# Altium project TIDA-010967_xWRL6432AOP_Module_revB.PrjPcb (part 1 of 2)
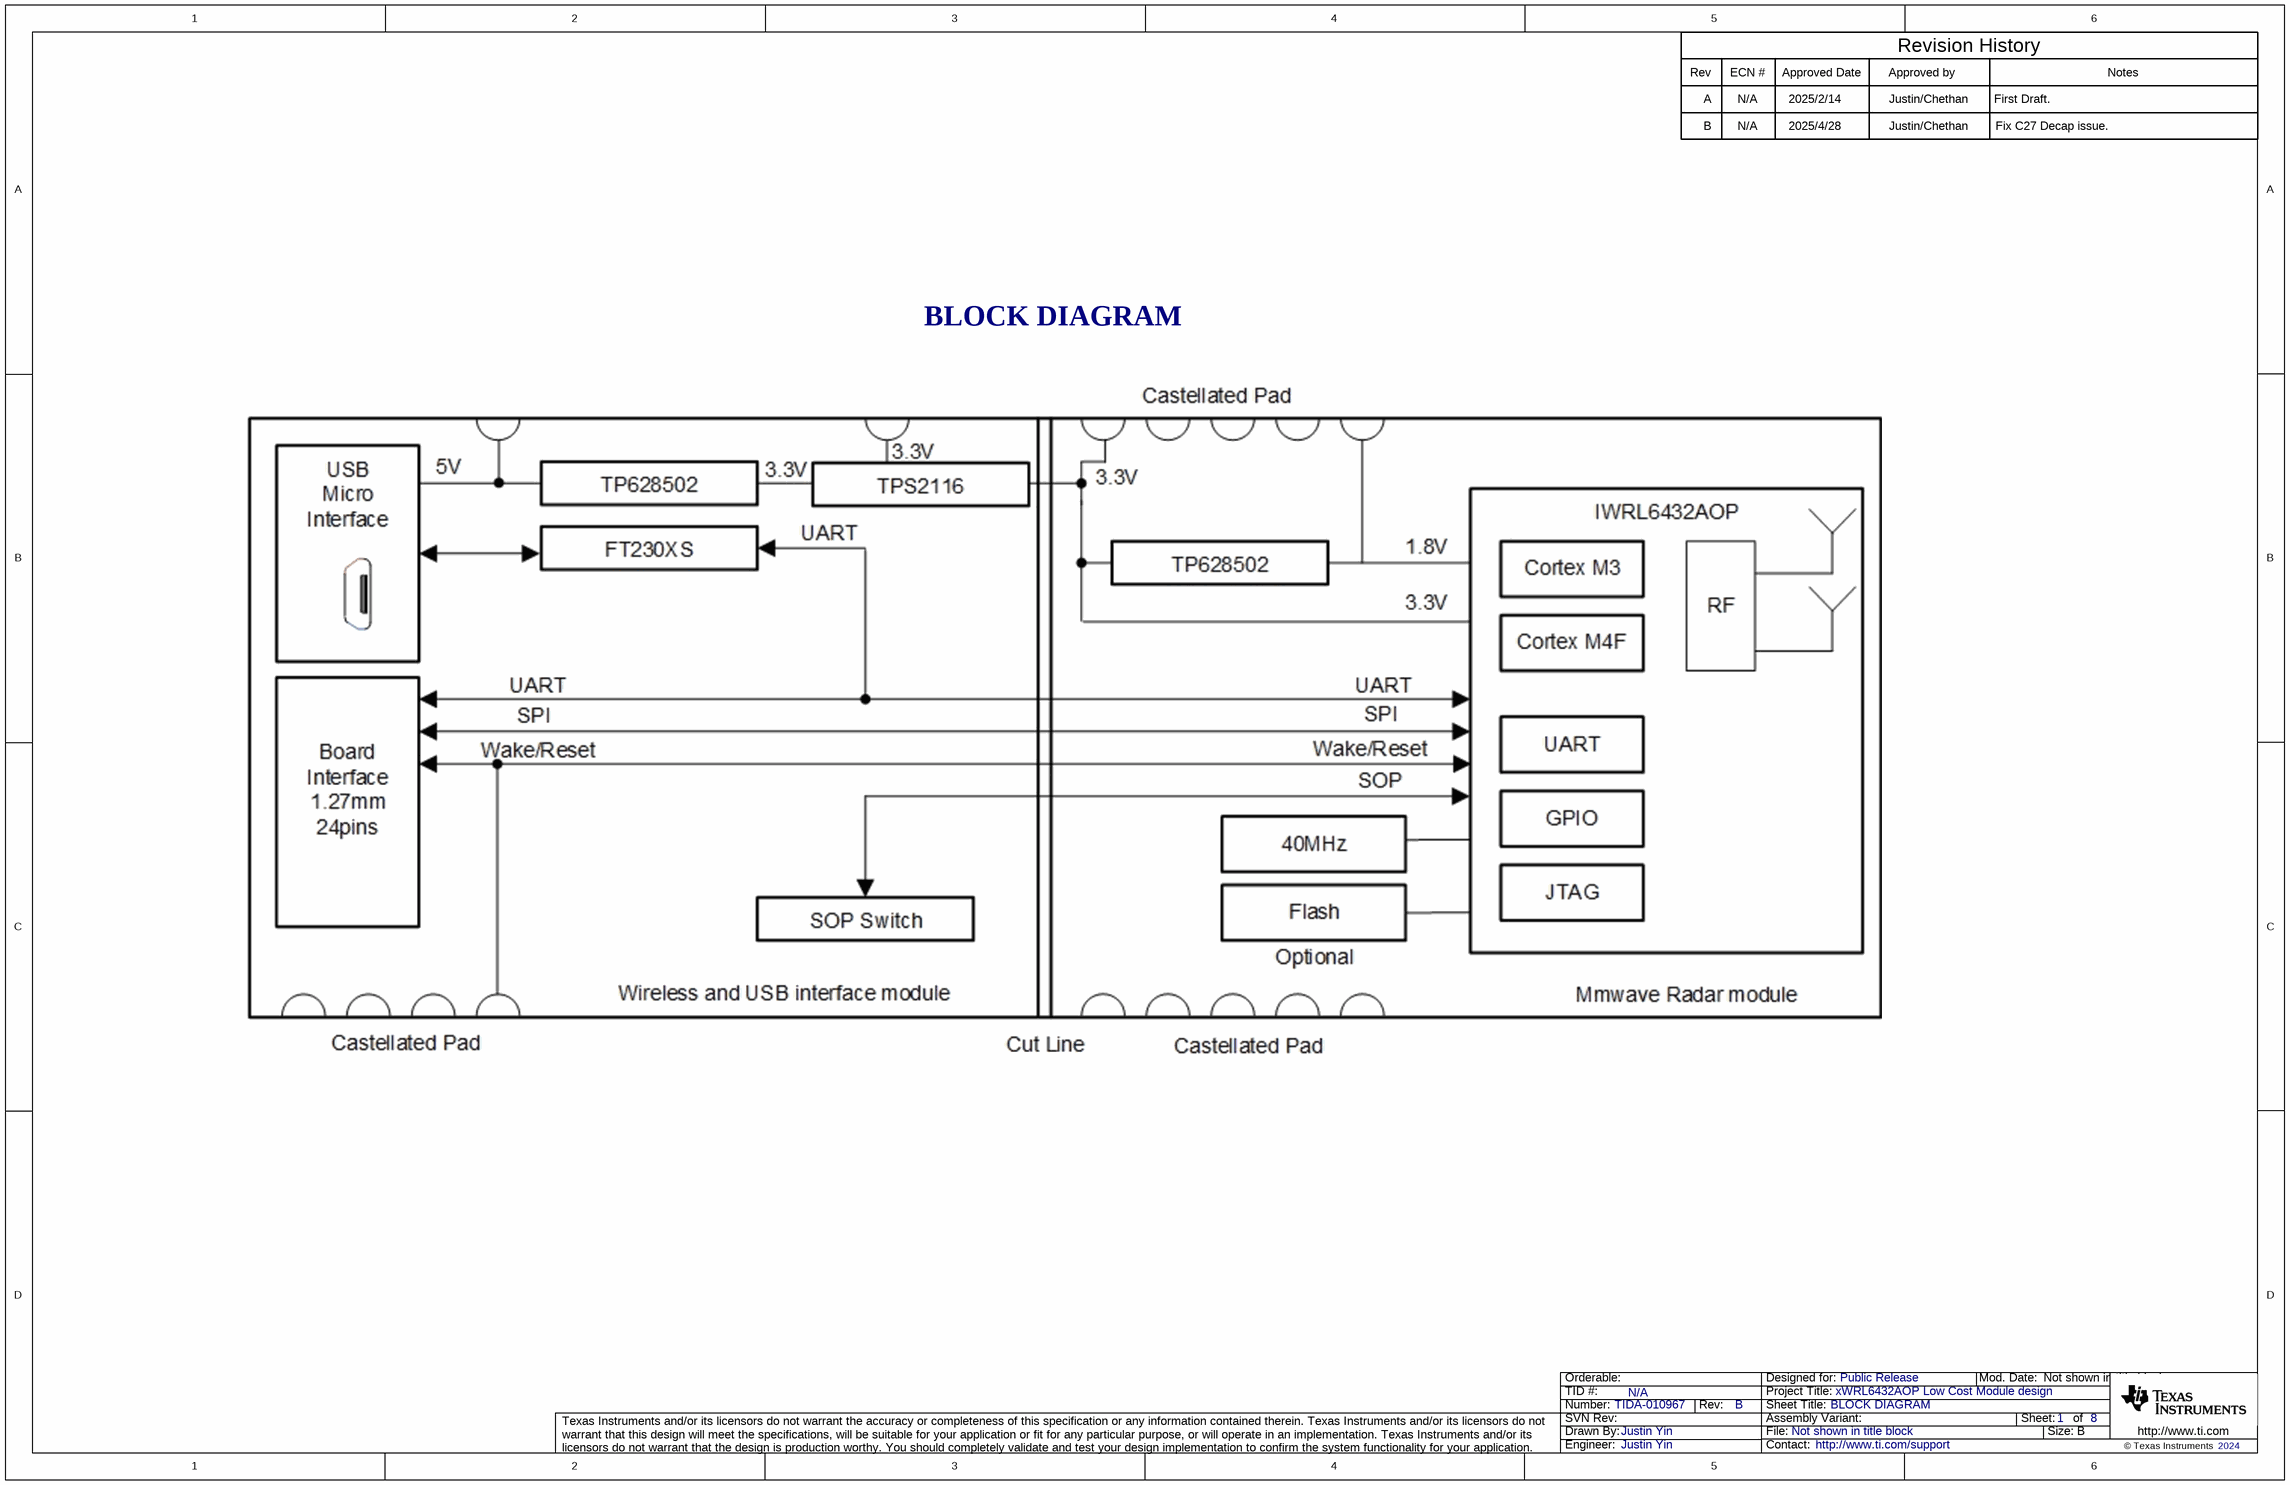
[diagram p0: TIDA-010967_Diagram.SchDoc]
CopyrightYear: 2024; PCB_Layout: Justin Yin; PCB_Rev: B; PRJ_Customer: Public Release; PRJ_Engineer: Justin Yin; PRJ_Number: TIDA-010967; PRJ_Title: xWRL6432AOP Low Cost Module design; SCH_Rev: B; TechSupport: http://www.ti.com/support; TID: N/A
8 sheets, 179 parts. Net scope: flat (ports and power ports of the same name join across sheets).
Board file: TIDA-010967_PCB.PcbDoc
Sheets:
  TIDA-010967_Diagram.SchDoc
  TIDA-010967_Table_Of_Contents.SchDoc
  TIDA-010967_USB_PWR_Connector.SchDoc
  TIDA-010967_DC_Regulators.SchDoc
  TIDA-010967_xWRL6432_Chip.SchDoc
  TIDA-010967_Decoupling_caps.SchDoc
  TIDA-010967_QSPI_Flash.SchDoc
  TIDA-010967_Hardware.SchDoc

## Sheet TIDA-010967_Diagram.SchDoc: BLOCK DIAGRAM
size 431 x 279 mm; Date: Not shown in title block; ApprovedBy: Not shown in title block; CheckedBy: Not shown in title block; Author: Not shown in title block; CompanyName: Not shown in title block; DrawnBy: Justin Yin; Organization: Not shown in title block; Address1: Not shown in title block; Address2: Not shown in title block; Address3: Not shown in title block; Address4: Not shown in title block; DocumentNumber: 1; Revision: Use project parameter SCH_Rev; SheetNumber: 1; SheetTotal: 8; PageSetup: Record=PageOptions¦CenterHorizontal=True¦CenterVertical=True¦PrintScale=1.00¦XCorrection=1.00¦YCorrection=1.00¦PrintKind=0¦BorderSize=5000000¦LeftOffset=0¦BottomOffset=0¦Orientation=2¦PaperLength=1000¦PaperWidth=1000¦Scale=100¦PaperSource=15¦PrintQuality=600¦MediaType=1¦DitherType=10¦PaperKind=Letter¦PrintScaleMode=1

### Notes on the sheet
- Rev
- A
- ECN #
- N/A
- 2025/2/14
- Approved Date
- Approved by
- Justin/Chethan
- Revision History
- First Draft.
- Notes
- B
- 2025/4/28
- Fix C27 Decap issue.
- BLOCK DIAGRAM

## Sheet TIDA-010967_Table_Of_Contents.SchDoc: TABLE OF CONTENTS
size 431 x 279 mm; Date: Not shown in title block; ApprovedBy: Not shown in title block; CheckedBy: Not shown in title block; Author: Not shown in title block; CompanyName: Not shown in title block; DrawnBy: Justin Yin; Engineer: Not shown in title block; Organization: Not shown in title block; Address1: Not shown in title block; Address2: Not shown in title block; Address3: Not shown in title block; Address4: Not shown in title block; DocumentNumber: 2; Revision: Use project parameter SCH_Rev; SheetNumber: 2; SheetTotal: 8; PageSetup: Record=PageOptions¦CenterHorizontal=True¦CenterVertical=True¦PrintScale=1.00¦XCorrection=1.00¦YCorrection=1.00¦PrintKind=0¦BorderSize=5000000¦LeftOffset=0¦BottomOffset=0¦Orientation=2¦PaperLength=1000¦PaperWidth=1000¦Scale=100¦PaperSource=15¦PrintQuality=600¦MediaType=1¦DitherType=10¦PaperKind=Letter¦PrintScaleMode=1
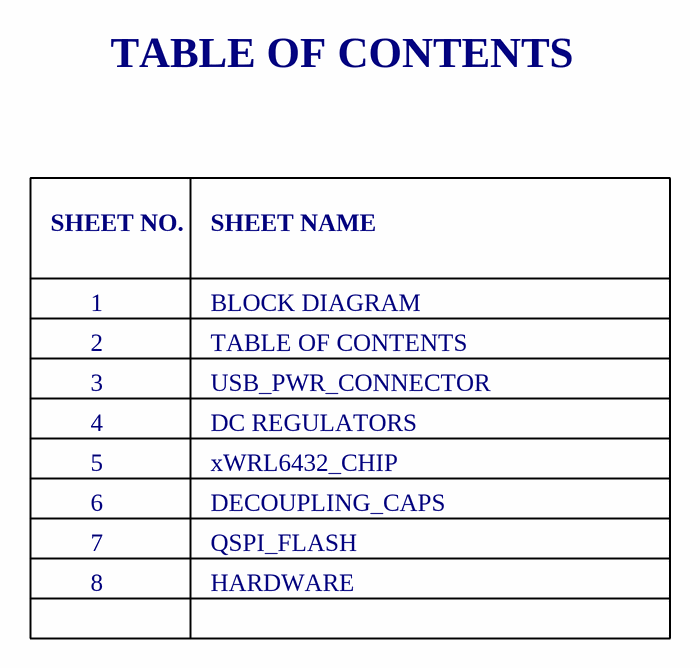
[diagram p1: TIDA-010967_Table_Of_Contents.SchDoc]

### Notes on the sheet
- TABLE OF CONTENTS
- SHEET NO.
- SHEET NAME
- 1
- 2
- 3
- BLOCK DIAGRAM
- USB_PWR_CONNECTOR
- 4
- 5
- DC REGULATORS
- xWRL6432_CHIP
- 7
- 8
- 6
- DECOUPLING_CAPS
- QSPI_FLASH
- HARDWARE

## Sheet TIDA-010967_USB_PWR_Connector.SchDoc: USB_PWR_Connector
size 431 x 279 mm; Date: Not shown in title block; ApprovedBy: Not shown in title block; CheckedBy: Not shown in title block; Author: Not shown in title block; CompanyName: Not shown in title block; DrawnBy: Justin Yin; Engineer: Not shown in title block; Organization: Not shown in title block; Address1: Not shown in title block; Address2: Not shown in title block; Address3: Not shown in title block; Address4: Not shown in title block; DocumentNumber: 3; Revision: Use project parameter SCH_Rev; SheetNumber: 3; SheetTotal: 8; PageSetup: Record=PageOptions¦CenterHorizontal=True¦CenterVertical=True¦PrintScale=1.00¦XCorrection=1.00¦YCorrection=1.00¦PrintKind=0¦BorderSize=5000000¦LeftOffset=0¦BottomOffset=0¦Orientation=2¦PaperLength=1000¦PaperWidth=1000¦Scale=100¦PaperSource=15¦PrintQuality=600¦MediaType=1¦DitherType=10¦PaperKind=Letter¦PrintScaleMode=1
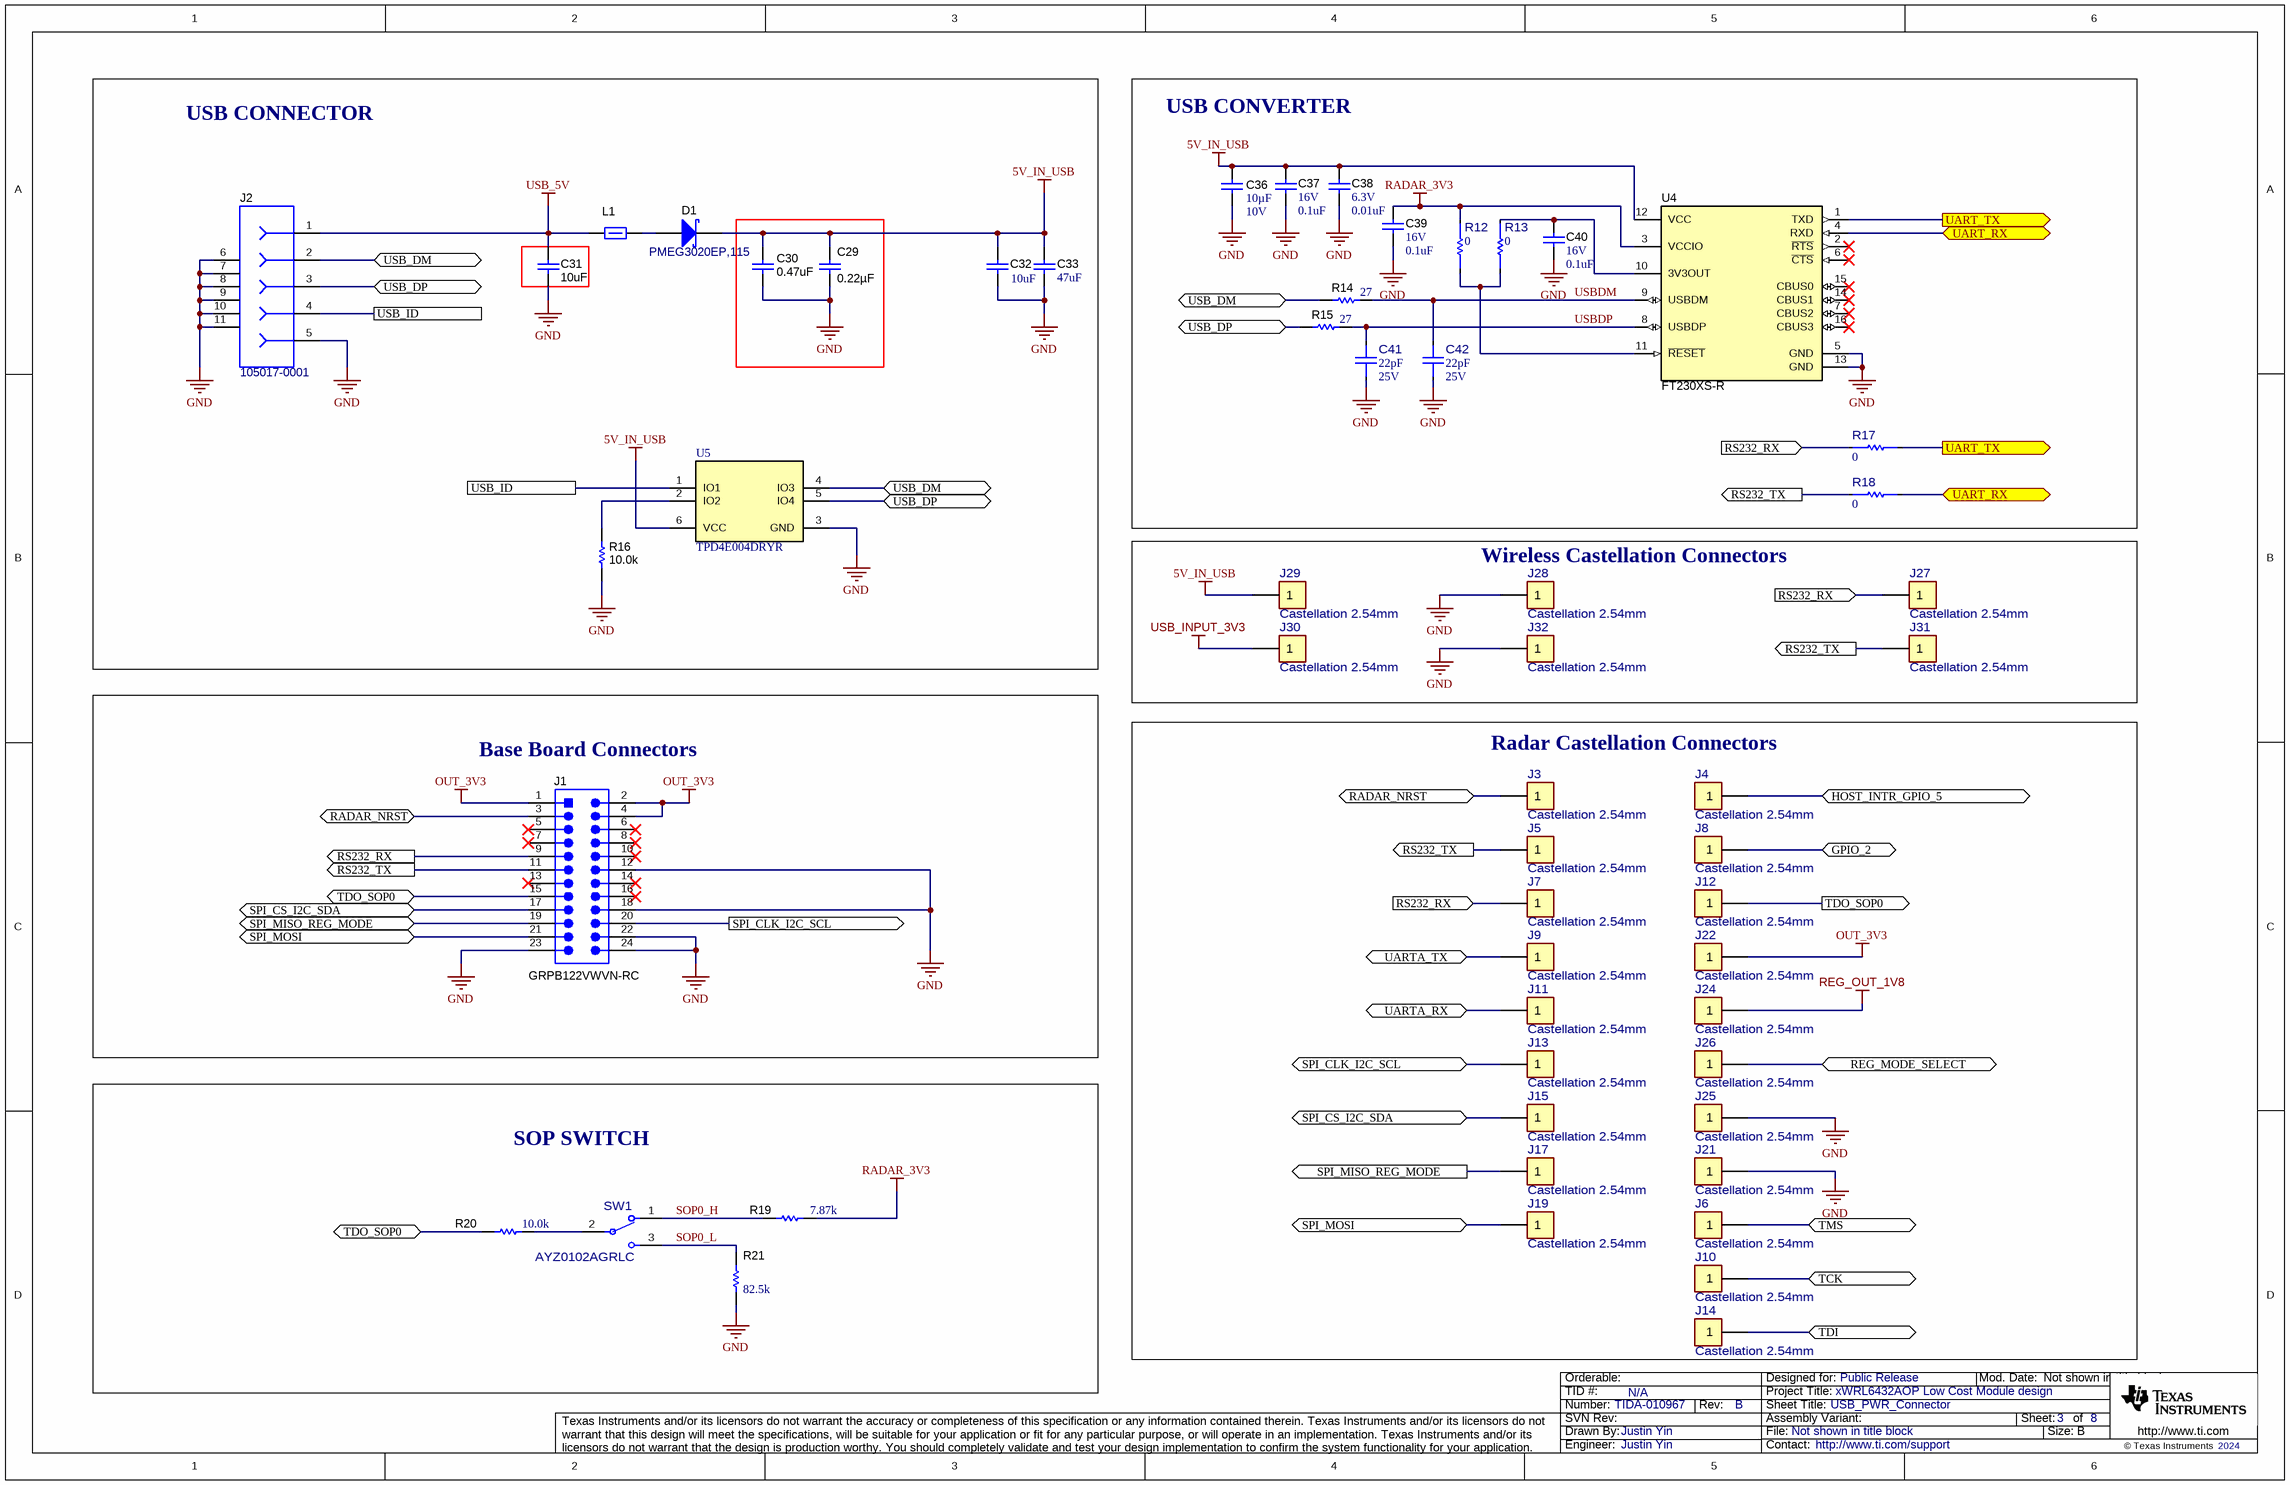
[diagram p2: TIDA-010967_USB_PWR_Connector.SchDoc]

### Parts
C29  ValueDisplayed: 0.22µF  [0402L]  (hidden comment: GCM155R71C224KE02D)
C30  ValueDisplayed: 0.47uF  [0402L]  (hidden comment: GCM155C71A474KE36D)
C31  ValueDisplayed: 10uF  [0603S]  (hidden comment: GRT188R61A106KE13D)
C32  ValueDisplayed: 10uF  [0402]  (hidden comment: GRM155R61A106ME11D)
C33  ValueDisplayed: 47uF  [1206_180]  (hidden comment: GRM31CR61A476KE15L)
C36  VDC_V: 10V  ValueDisplayed: 10µF  [0402_080]  (hidden comment: 0402ZD106MAT2A)
C37  VDC_V: 16V  ValueDisplayed: 0.1uF  [0201_033]  (hidden comment: GRM033R61C104KE84D)
C38  VDC_V: 6.3V  ValueDisplayed: 0.01uF  [0201]  (hidden comment: GRM033R70J103KA01D)
C39  VDC_V: 16V  ValueDisplayed: 0.1uF  [0201_033]  (hidden comment: GRM033R61C104KE84D)
C40  VDC_V: 16V  ValueDisplayed: 0.1uF  [0201_033]  (hidden comment: GRM033R61C104KE84D)
C41  ValueDisplayed: 22pF  VDC_V: 25V  [FP-GCM0335C1E220JA16D_0201-MFG]  (hidden comment: GCM0335C1E220JA16D)
C42  ValueDisplayed: 22pF  VDC_V: 25V  [FP-GCM0335C1E220JA16D_0201-MFG]  (hidden comment: GCM0335C1E220JA16D)
D1  PMEG3020EP,115  [SOD-128]
J1  GRPB122VWVN-RC  [Sullins_GRPB122VWVN]
J2  105017-0001  [CONN_105017-0001]
J3  Castellation 2.54mm  [FP-Castellation 2.54mm_75mills]
J4  Castellation 2.54mm  [FP-Castellation 2.54mm_75mills]
J5  Castellation 2.54mm  [FP-Castellation 2.54mm_75mills]
J6  Castellation 2.54mm  [FP-Castellation 2.54mm_75mills]
J7  Castellation 2.54mm  [FP-Castellation 2.54mm_75mills]
J8  Castellation 2.54mm  [FP-Castellation 2.54mm_75mills]
J9  Castellation 2.54mm  [FP-Castellation 2.54mm_75mills]
J10  Castellation 2.54mm  [FP-Castellation 2.54mm_75mills]
J11  Castellation 2.54mm  [FP-Castellation 2.54mm_75mills]
J12  Castellation 2.54mm  [FP-Castellation 2.54mm_75mills]
J13  Castellation 2.54mm  [FP-Castellation 2.54mm_75mills]
J14  Castellation 2.54mm  [FP-Castellation 2.54mm_75mills]
J15  Castellation 2.54mm  [FP-Castellation 2.54mm_75mills]
J17  Castellation 2.54mm  [FP-Castellation 2.54mm_75mills]
J19  Castellation 2.54mm  [FP-Castellation 2.54mm_75mills]
J21  Castellation 2.54mm  [FP-Castellation 2.54mm_75mills]
J22  Castellation 2.54mm  [FP-Castellation 2.54mm_75mills]
J24  Castellation 2.54mm  [FP-Castellation 2.54mm_75mills]
J25  Castellation 2.54mm  [FP-Castellation 2.54mm_75mills]
J26  Castellation 2.54mm  [FP-Castellation 2.54mm_75mills]
J27  Castellation 2.54mm  [FP-Castellation 2.54mm_75mills]
J28  Castellation 2.54mm  [FP-Castellation 2.54mm_75mills]
J29  Castellation 2.54mm  [FP-Castellation 2.54mm_75mills]
J30  Castellation 2.54mm  [FP-Castellation 2.54mm_75mills]
J31  Castellation 2.54mm  [FP-Castellation 2.54mm_75mills]
J32  Castellation 2.54mm  [FP-Castellation 2.54mm_75mills]
L1  BLM15PD300SZ1D  [0402L]  (value not drawn)
R12  value 0  [FP-RC0402JR-070RP_0402-MFG]  (hidden comment: RC0402JR-070RP)
R13  value 0  [FP-RC0402JR-070RP_0402-MFG]  (hidden comment: RC0402JR-070RP)
R14  ValueDisplayed: 27  [0201]  (hidden comment: RC0201JR-0727RL)
R15  ValueDisplayed: 27  [0201]  (hidden comment: RC0201JR-0727RL)
R16  ValueDisplayed: 10.0k  [0402L]  (hidden comment: CRCW040210K0FKED)
R17  value 0  [FP-RC0402JR-070RP_0402-MFG]  (hidden comment: RC0402JR-070RP)
R18  value 0  [FP-RC0402JR-070RP_0402-MFG]  (hidden comment: RC0402JR-070RP)
R19  ValueDisplayed: 7.87k  [0402L]  (hidden comment: CRCW04027K87FKED)
R20  ValueDisplayed: 10.0k  [0402L]  (hidden comment: CRCW040210K0FKED)
R21  ValueDisplayed: 82.5k  [0402L]  (hidden comment: CRCW040282K5FKED)
SW1  AYZ0102AGRLC  [FP-AYZ0102AGRLC_SMT_SW_7MM2_5MM3-MFG]
U4  FT230XS-R  [SSOP-16]
U5  TPD4E004DRYR  [DRY0006A]

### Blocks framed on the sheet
USB CONNECTOR: C29-C33 D1 J2 L1 R16 U5
USB CONVERTER: C36-C42 R12-R15 R17 R18 U4
Wireless Castellation Connectors: J27-J32
Base Board Connectors: J1
Radar Castellation Connectors: J3-J15 J17 J19 J21 J22 J24-J26
SOP SWITCH: R19-R21 SW1

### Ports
GPIO_2 (bidir), HOST_INTR_GPIO_5 (bidir), RADAR_NRST (bidir), REG_MODE_SELECT (bidir), RS232_RX (in), RS232_RX (out), RS232_TX (out), SPI_CLK_I2C_SCL (bidir), SPI_CLK_I2C_SCL (out), SPI_CS_I2C_SDA (bidir), SPI_MISO_REG_MODE (bidir), SPI_MISO_REG_MODE (out), SPI_MOSI (bidir), TCK (bidir), TDI (bidir), TDO_SOP0 (bidir), TDO_SOP0 (out), TMS (bidir), UART_RX (bidir), UART_TX (out), UARTA_RX (bidir), UARTA_TX (bidir), USB_DM (bidir), USB_DP (bidir), USB_ID

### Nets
5V_IN_USB: C29.2 C30.1 C32.2 C33.1 C36.1 C37.1 C38.1 D1.1(K) J29.1 U4.12(VCC) U5.6(VCC)
GND: C29.1 C30.2 C31.1 C32.1 C33.2 C36.2 C37.2 C38.2 C39.2 C40.2 C41.1 C42.1 J1.12 J1.18 J1.22 J1.23 J1.24 J2.5 J2.6 J2.7 J2.8 J2.9 J2.10 J2.11 J21.1 J25.1 J28.1 J32.1 R16.1 R21.1 U4.5(GND) U4.13(GND) U5.3(GND)
OUT_3V3: J1.1 J1.2 J1.4 J22.1
RADAR_3V3: C39.1 R12.1 R19.2 U4.3(VCCIO)
REG_OUT_1V8: J24.1
USB_5V: C31.2 J2.1 L1.1
USB_INPUT_3V3: J30.1
GPIO_2: J8.1 ; port GPIO_2
HOST_INTR_GPIO_5: J4.1 ; port HOST_INTR_GPIO_5
RADAR_NRST: J1.3 J3.1 ; port RADAR_NRST
REG_MODE_SELECT: J26.1 ; port REG_MODE_SELECT
RS232_RX: J1.9 J7.1 J27.1 R17.1 ; port RS232_RX
RS232_TX: J1.11 J5.1 J31.1 R18.1 ; port RS232_TX
SOP0_H: R19.1 SW1.1
SOP0_L: R21.2 SW1.3
SPI_CLK_I2C_SCL: J1.20 J13.1 ; port SPI_CLK_I2C_SCL
SPI_CS_I2C_SDA: J1.17 J15.1 ; port SPI_CS_I2C_SDA
SPI_MISO_REG_MODE: J1.19 J17.1 ; port SPI_MISO_REG_MODE
SPI_MOSI: J1.21 J19.1 ; port SPI_MOSI
TCK: J10.1 ; port TCK
TDI: J14.1 ; port TDI
TDO_SOP0: J1.15 J12.1 R20.1 ; port TDO_SOP0
TMS: J6.1 ; port TMS
UART_RX: R18.2 U4.4(RXD) ; port UART_RX
UART_TX: R17.2 U4.1(TXD) ; port UART_TX
UARTA_RX: J11.1 ; port UARTA_RX
UARTA_TX: J9.1 ; port UARTA_TX
USB_DM: J2.2 R14.1 U5.4(IO3) ; port USB_DM
USB_DP: J2.3 R15.1 U5.5(IO4) ; port USB_DP
USB_ID: J2.4 U5.1(IO1) ; port USB_ID
USBDM: C42.2 R14.2 U4.9(USBDM)
USBDP: C41.2 R15.2 U4.8(USBDP)
NetC40_1: C40.1 R13.1 U4.10(3V3OUT)
NetD1_2: D1.2(A) L1.2
NetR12_2: R12.2 R13.2 U4.11(~{RESET})
NetR16_2: R16.2 U5.2(IO2)
NetR20_2: R20.2 SW1.2(C)

Not connected (* = marked no-connect by the designer): J1 5* 6* 7* 8* 10* 13* 14* 16*; U4 2(~{RTS})* 6(~{CTS})* 7(CBUS2)* 14(CBUS1)* 15(CBUS0)* 16(CBUS3)*

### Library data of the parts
C29 = CMP-0078265-1: CAP, CERM, 0.22 µF, 16 V,+/- 10%, X7R, AEC-Q200 Grade 1, 0402; Manufacturer: MuRata; TaMin_C: -55°C; Polarized: N; SizeAreaWB_mm2: 3; U/M: EA; Value: 0.22uF; TaMax_C: 125°C; SizeZ_mm: 0.6; SizeX_mm: 1; SizeY_mm: 0.5; Cap_Case: 0402; Value2: 16V; CompType: Capacitor; AEC Qualified: Y; Cap_F: 220nF; AEC Category: Q200
C30 = CMP-0064967-2: CAP, CERM, 0.47 uF, 10 V,+/- 10%, X7S, 0402; Manufacturer: MuRata; Polarized: N; Value: 0.47uF; U/M: EA; Cap_F: 470nF; Value1: Unknown; VDC_V: 10V; TaMin_C: -55°C; TaMax_C: 125°C; Cap_Case: 0402; SizeArea_mm2: 0.5; SizeAreaWB_mm2: 3; SizeX_mm: 1; SizeZ_mm: 0.6; AEC Category: Q200
C31 = CMP-0007497-5: CAP, CERM, 10 uF, 10 V, +/- 10%, X5R, 0603; Manufacturer: MuRata; Polarized: N; Value: 10uF; U/M: EA; Cap_F: 10µF; Tolerance_%: 20%; Value1: Unknown; VDC_V: 10V; TempCo: X7R; TaMin_C: -55°C; TaMax_C: 125°C; Cap_Case: 0603; SizeArea_mm2: 1.28; SizeAreaWB_mm2: 4.68; SizeX_mm: 1.6; SizeY_mm: 0.8; SizeZ_mm: 1; AEC Category: Q200
C32 = CMP-0006564-3: CAP, CERM, 10 uF, 10 V, +/- 20%, X5R, 0402; Manufacturer: MuRata; TaMin_C: -55°C; Polarized: N; SizeAreaWB_mm2: 3; Value1: Unknown; U/M: EA; Value: 10uF; TaMax_C: 85°C; SizeZ_mm: 0.6; SizeX_mm: 1; SizeY_mm: 0.5; Value2: 10V; Cap_F: 10µF; AEC Category: Q200
C33 = CMP-0008944-2: CAP, CERM, 47 uF, 10 V, +/- 10%, X5R, 1206; Manufacturer: MuRata; TaMin_C: -55°C; Polarized: N; SizeAreaWB_mm2: 10.92; Value1: Unknown; U/M: EA; Value: 47uF; TaMax_C: 85°C; SizeZ_mm: 1.8; SizeX_mm: 3.2; SizeY_mm: 1.6; Cap_Case: 1206; Value2: 10V; SizeArea_mm2: 5.12; Cap_F: 47µF; AEC Category: Q200
C36 = CMP-0078623-1: CAP, CERM, 10 µF, 10 V,+/- 20%, X5R, 0402; Manufacturer: AVX; Value: 10uF; Polarized: N; SizeAreaWB_mm2: 3; SizeArea_mm2: 0.5; AEC Category: Q200; TaMax_C: 85°C; SizeZ_mm: 0.8; TaMin_C: -55°C; U/M: EA; SizeX_mm: 1
C37 C39 C40 = CMP-0009717-2: CAP, CERM, 0.1 uF, 16 V, +/- 10%, X5R, 0201; Manufacturer: MuRata; TaMin_C: -55°C; Polarized: N; SizeAreaWB_mm2: 2.08; Value1: Unknown; U/M: EA; Value: 0.1uF; TaMax_C: 85°C; SizeZ_mm: 0.33; SizeX_mm: 0.6; SizeY_mm: 0.3; Cap_Case: 0201; SizeArea_mm2: 0.18; Cap_F: 100nF; AEC Category: Q200
C38 = CMP-0009720-2: CAP, CERM, 0.01 uF, 6.3 V, +/- 10%, X7R, 0201; Manufacturer: MuRata; TaMin_C: -55°C; Polarized: N; SizeAreaWB_mm2: 2.08; Value1: Unknown; U/M: EA; Value: 0.01uF; TaMax_C: 125°C; SizeZ_mm: 0.26; SizeX_mm: 0.6; SizeY_mm: 0.3; SizeArea_mm2: 0.18; Cap_F: 10nF; AEC Category: Q200
C41 C42 = CMP-0124498-1: Ceramic Capacitor for Automotive 22pF  ±5% 25VDC C0G 0201 Paper T/R; Manufacturer: Murata; AEC Grade: Grade 1; AEC Qualified: Yes; SizeZ_mm: 0.33mm; TempCo: 30ppm/°C; Tolerance_%: 0.05%
D1 = CMP-0078758-2: Diode, Schottky, 30 V, 2 A, AEC-Q101, SOD-128; Manufacturer: Nexperia; Value2: 0.36V; SizeAreaWB_mm2: 19.6; Io_A: 2A; Value: 30V; AEC Qualified: Y; TJmax_C: 150°C; SizeX_mm: 4.6; AEC Category: Q101; SizeY_mm: 2.5; SizeArea_mm2: 11.5; Vf_V: 3.6dV; SizeZ_mm: 1.1
J1 = CMP-0054595-1: Header, 1.27mm, 12x2, Gold, TH; Manufacturer: Sullins Connector Solutions; CNHeader: TRUE; Current_A: 1A; Gender: Male; Row_Count: 2; RowSpacing_mm: 1.27; CT: FALSE; Cert_UL: Y
J2 = CMP-0055293-1: Connector, Receptacle, Micro-USB Type B, R/A, Bottom Mount SMT; Manufacturer: Molex; CNHeader: FALSE; CompType: USB; CT: TRUE; Gender: Female; Green_Lifecycle: Active; Green_REACh: Passed
J3-J15 J17 J19 J21 J22 J24-J32 = CMP-0124126-3: Manufacturer: Altium; Conn Gender: NA
L1 = CMP-0078934-1: Inductor, Ferrite Bead, Ferrite, 2.2 A, 0.035 ohm, AEC-Q200 Grade 1, SMD; Manufacturer: MuRata; AEC Category: Q200; AEC Grade: 1; AEC Qualified: Y; DCR_ohm: 0.035; Imax_A: 2.2A; SizeArea_mm2: 0.5; SizeAreaWB_mm2: 3; SizeZ_mm: 0.6
R12 R13 R17 R18 = CMP-0093147-1: Res Jumper Thick Film 0402 0 Ohm 5% 1/16W Molded SMD Paper T/R; Manufacturer: Yageo; AEC Qualified: No; Power_W: 63mW; SizeZ_mm: 0.4mm; VDC_V: 50V
R14 R15 = CMP-0027082-3: RES, 27, 5%, 0.05 W, 0201; Manufacturer: Yageo America; Power_W: 50mW; TempCo: 200 ppm/C; Value_Code: 27R0; U/M: EA; Value: 27; EIA_Code: E24; SizeX_mm: 0.6; SizeY_mm: 0.3; SizeZ_mm: 0.26; Value2: 0.05W; SizeArea_mm2: 0.18; AEC Qualified: N; VDC_V: 25V; AEC Category: Q200
R16 R20 = CMP-0025958-3: RES, 10.0 k, 1%, 0.063 W, AEC-Q200 Grade 0, 0402; Manufacturer: Vishay-Dale; Power_W: 63mW; TempCo: 100 ppm/C; Value_Code: 10k0; Value: 10.0k; EIA_Code: E96; Res_ohm: 10k; SizeX_mm: 1; SizeY_mm: 0.5; SizeZ_mm: 0.6; Value2: 0.063W; AEC Qualified: Y; VDC_V: 50V; AEC Category: Q200; AEC Grade: 0
R19 = CMP-0026557-2: RES, 7.87 k, 1%, 0.063 W, AEC-Q200 Grade 0, 0402; Manufacturer: Vishay-Dale; Power_W: 63mW; TempCo: 100 ppm/C; Value_Code: 7k87; Value: 7.87k; EIA_Code: E96; SizeX_mm: 1; SizeY_mm: 0.5; SizeZ_mm: 0.6; Value2: 0.063W; AEC Qualified: Y; VDC_V: 50V; AEC Grade: 0; AEC Category: Q200
R21 = CMP-0026574-2: RES, 82.5 k, 1%, 0.063 W, AEC-Q200 Grade 0, 0402; Manufacturer: Vishay-Dale; Power_W: 63mW; TempCo: 100 ppm/C; Value_Code: 82k5; Value: 82.5k; EIA_Code: E96; SizeX_mm: 1; SizeY_mm: 0.5; SizeZ_mm: 0.6; Value2: 0.063W; AEC Qualified: Y; VDC_V: 50V; AEC Grade: 0; AEC Category: Q200
SW1 = CMP-0096333-1: Slide Switch SPDT Surface Mount, Right Angle; Manufacturer: C&K Switches; Coil Resistance_ohm: 80mΩ; SizeZ_mm: 1.5mm; AEC Qualified: No; VDC_V: 12V; Contact Current Rating: 100mA; Electromechanical Life: 10000Cycles
U4 = CMP-0065473-1: USB to UART, SSOP-16; Manufacturer: FTDI; SizeZ_mm: 1.75; SizeX_mm: 5.99; SizeY_mm: 4.9; SizeArea_mm2: 29.351; SizeAreaWB_mm2: 55.131
U5 = CMP-0043115-3: 4-Channel ESD Protection Array for High-Speed Data Interfaces, DRY0006A (USON-6); Manufacturer: Texas Instruments; IO Leakage Current(nA): 1; USB High Speed: TRUE; IO Capacitance(Typ)(pF): 1.6; Eco-Plan: Green (RoHS & no Sb/Br); IEC 61000-4-2 Contact(+/- kV): 8; Breakdown Voltage(Min)(V): 6; IEC 61000-4-2 Air-Gap(+/- kV): 12; AEC Category: Q200; AEC Qualified: N; CompType: IC; SizeAreaWB_mm2: 4.9; SizeArea_mm2: 1.45; SizeX_mm: 1.0; SizeZ_mm: 0.6; Rating: Catalog

## Sheet TIDA-010967_DC_Regulators.SchDoc: DC_REGULATORS
size 431 x 279 mm; Date: Not shown in title block; ApprovedBy: Not shown in title block; CheckedBy: Not shown in title block; Author: Not shown in title block; CompanyName: Not shown in title block; DrawnBy: Justin Yin; Engineer: Not shown in title block; Organization: Not shown in title block; Address1: Not shown in title block; Address2: Not shown in title block; Address3: Not shown in title block; Address4: Not shown in title block; DocumentNumber: 4; Revision: Use project parameter SCH_Rev; SheetNumber: 4; SheetTotal: 8; PageSetup: Record=PageOptions¦CenterHorizontal=True¦CenterVertical=True¦PrintScale=1.00¦XCorrection=1.00¦YCorrection=1.00¦PrintKind=0¦BorderSize=5000000¦LeftOffset=0¦BottomOffset=0¦Orientation=2¦PaperLength=1000¦PaperWidth=1000¦Scale=100¦PaperSource=15¦PrintQuality=600¦MediaType=1¦DitherType=10¦PaperKind=Letter¦PrintScaleMode=1
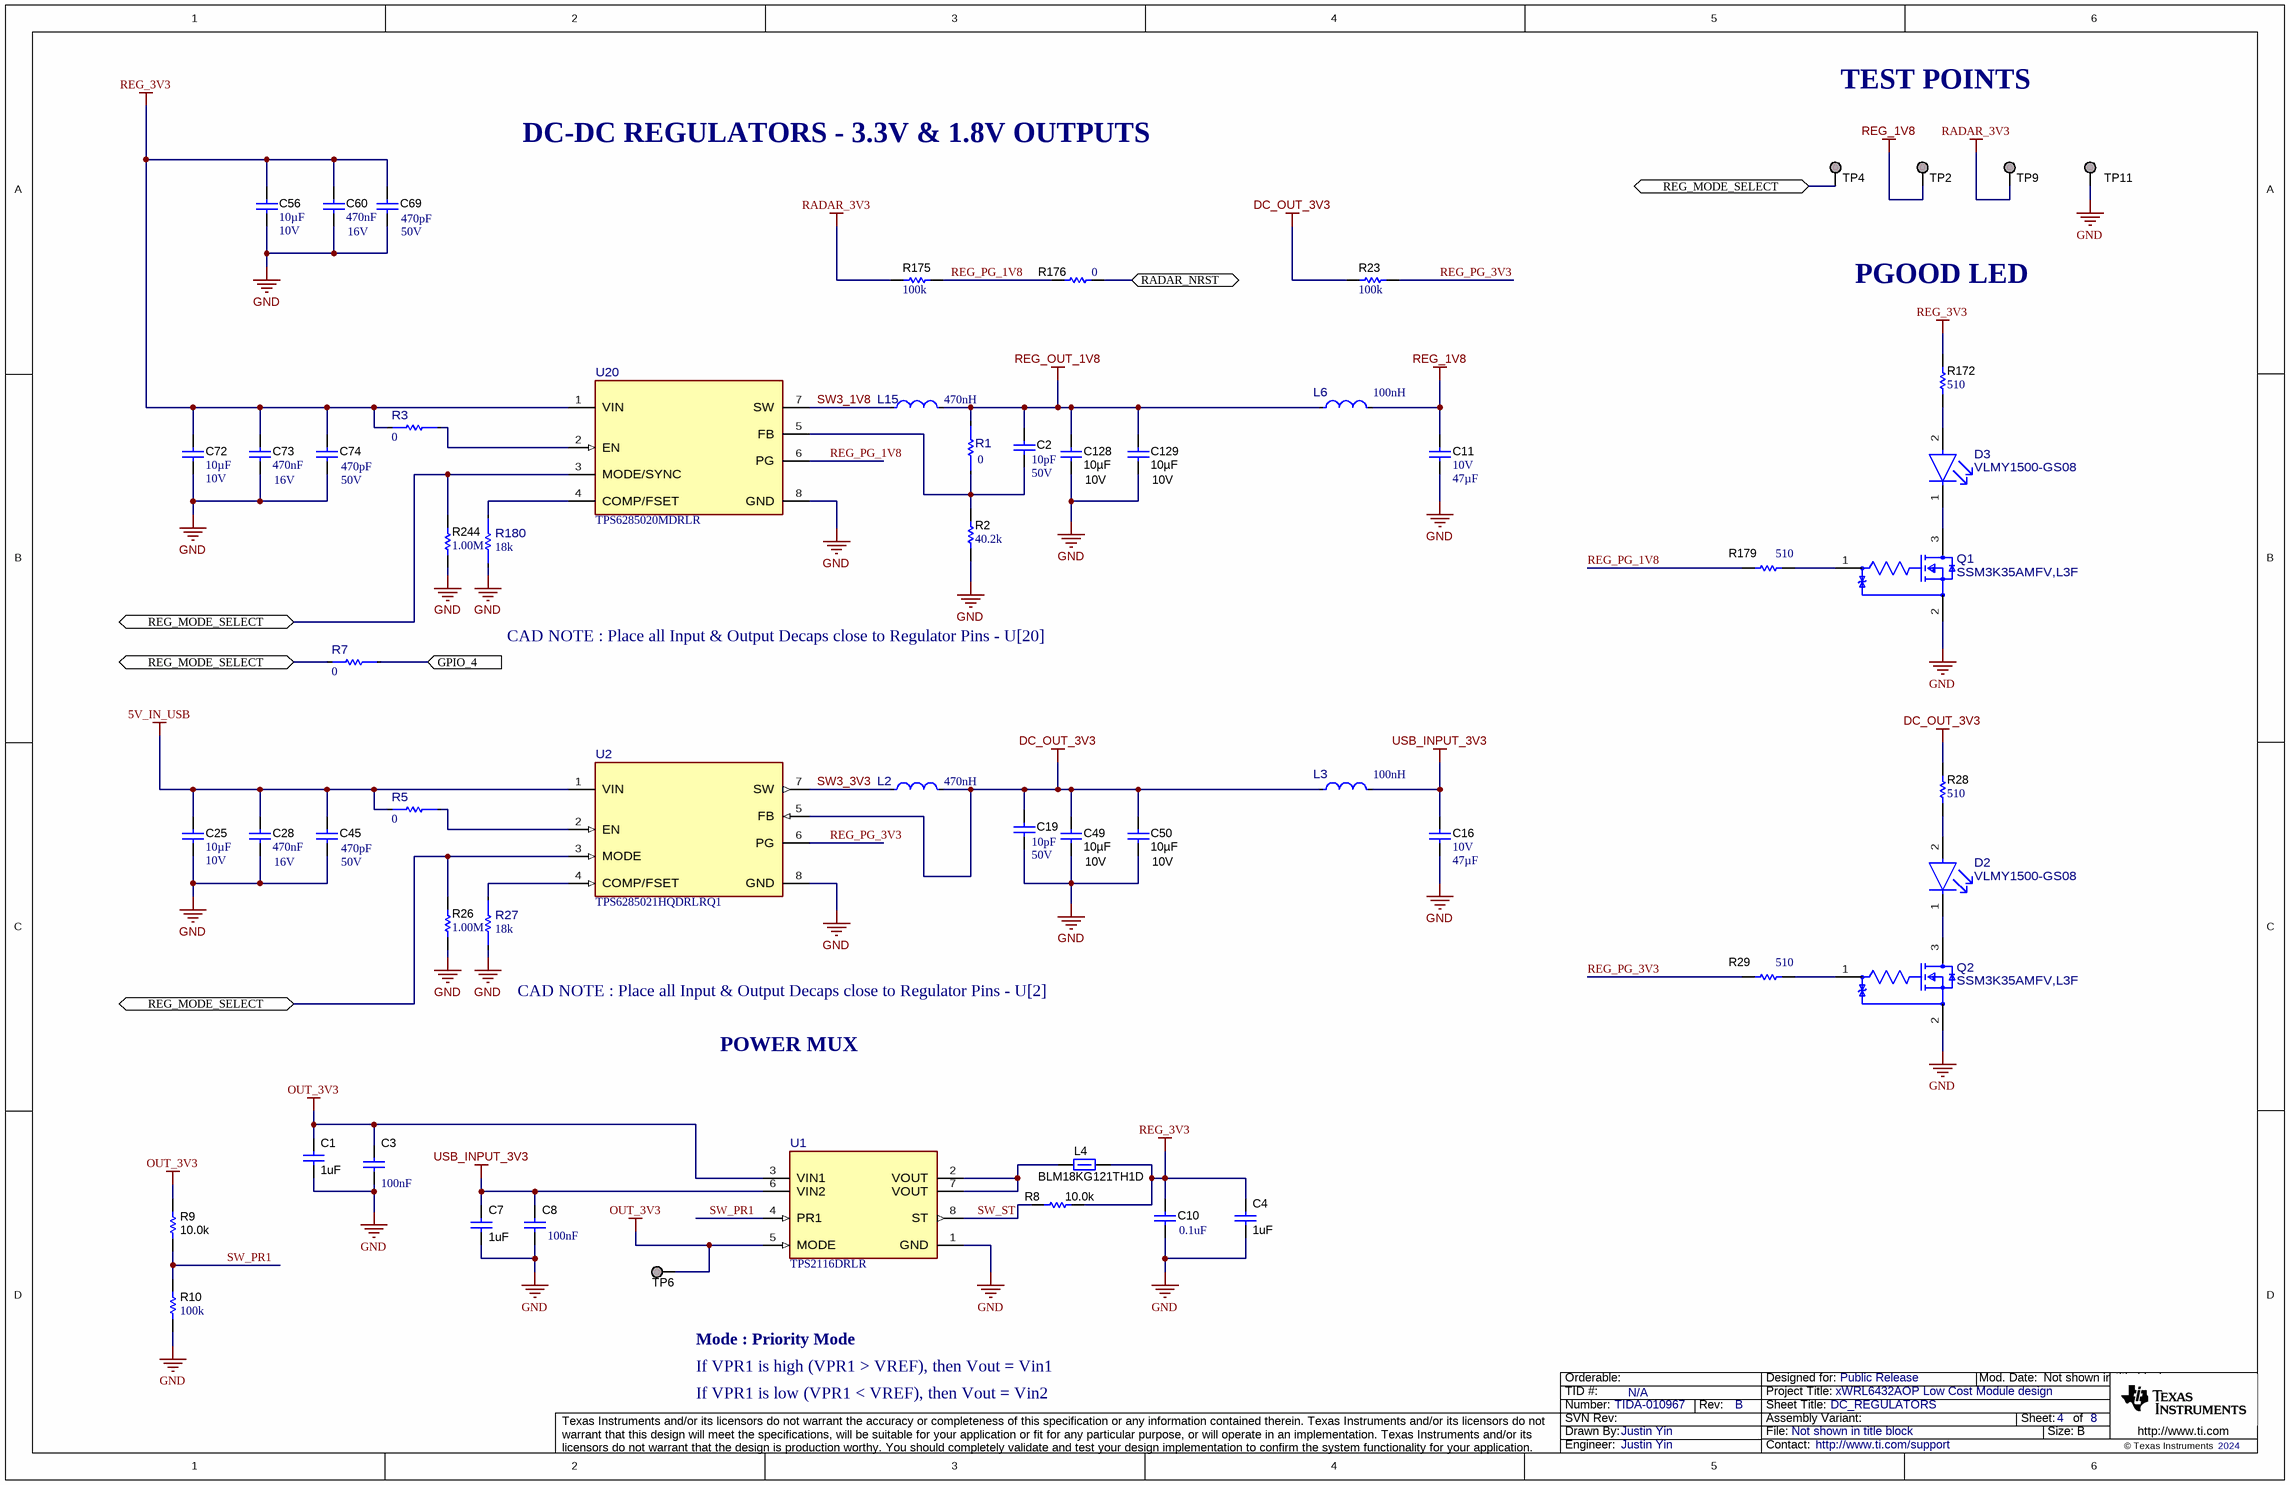
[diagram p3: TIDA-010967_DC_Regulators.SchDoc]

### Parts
C1  ValueDisplayed: 1uF  [0402L]  (hidden comment: GRT155C81A105KE01D)
C2  VDC_V: 50V  ValueDisplayed: 10pF  [0402L]  (hidden comment: GRM1555C1H100JA01D)
C3  Cap_F: 100nF  [0402]  (hidden comment: GCM155R71H104KE02D)
C4  ValueDisplayed: 1uF  [0402L]  (hidden comment: GRT155C81A105KE01D)
C7  ValueDisplayed: 1uF  [0402L]  (hidden comment: GRT155C81A105KE01D)
C8  Cap_F: 100nF  [0402]  (hidden comment: GCM155R71H104KE02D)
C10  ValueDisplayed: 0.1uF  [0402]  (hidden comment: GCM155R71H104KE02D)
C11  VDC_V: 10V  ValueDisplayed: 47µF  [0805_HV]  (hidden comment: GRM21BR61A476ME15L)
C16  VDC_V: 10V  ValueDisplayed: 47µF  [0805_HV]  (hidden comment: GRM21BR61A476ME15L)
C19  VDC_V: 50V  ValueDisplayed: 10pF  [0402L]  (hidden comment: GRM1555C1H100JA01D)
C25  Cap_F: 10µF  VDC_V: 10V  [0603_HV]  (hidden comment: GRM188Z71A106MA73D)
C28  Value2: 16V  Cap_F: 470nF  [0603L]  (hidden comment: GRM188R71C474KA88D)
C45  Value2: 50V  ValueDisplayed: 470pF  [0402L]  (hidden comment: GRM1555C1H471JA01D)
C49  Value2: 10V  Cap_F: 10µF  [0603L]  (hidden comment: GRM188Z71A106MA73D)
C50  Value2: 10V  Cap_F: 10µF  [0603L]  (hidden comment: GRM188Z71A106MA73D)
C56  Cap_F: 10µF  VDC_V: 10V  [0603_HV]  (hidden comment: GRM188Z71A106MA73D)
C60  Value2: 16V  Cap_F: 470nF  [0603L]  (hidden comment: GRM188R71C474KA88D)
C69  Value2: 50V  ValueDisplayed: 470pF  [0402L]  (hidden comment: GRM1555C1H471JA01D)
C72  Cap_F: 10µF  VDC_V: 10V  [0603_HV]  (hidden comment: GRM188Z71A106MA73D)
C73  Value2: 16V  Cap_F: 470nF  [0603L]  (hidden comment: GRM188R71C474KA88D)
C74  Value2: 50V  ValueDisplayed: 470pF  [0402L]  (hidden comment: GRM1555C1H471JA01D)
C128  Value2: 10V  Cap_F: 10µF  [0603L]  (hidden comment: GRM188Z71A106MA73D)
C129  Value2: 10V  Cap_F: 10µF  [0603L]  (hidden comment: GRM188Z71A106MA73D)
D2  VLMY1500-GS08  [FP-VLMY1500-GS08_0402-MFG]
D3  VLMY1500-GS08  [FP-VLMY1500-GS08_0402-MFG]
L2  Ind_H: 470nH  [FP-DFE201210U-R47M=P2_0805 (2012)-MFG]  (hidden comment: DFE201210U-R47M=P2)
L3  Ind_H: 100nH  [FP-SPH201610UR10MT_SMT_IND_2MM0_1MM6-MFG]  (hidden comment: SPH201610UR10MT)
L4  BLM18KG121TH1D  [0603L]
L6  Ind_H: 100nH  [FP-SPH201610UR10MT_SMT_IND_2MM0_1MM6-MFG]  (hidden comment: SPH201610UR10MT)
L15  Ind_H: 470nH  [FP-DFE201210U-R47M=P2_0805 (2012)-MFG]  (hidden comment: DFE201210U-R47M=P2)
Q1  SSM3K35AMFV,L3F  [FP-SSM3K35AMFV,L3F_SOT-723-MFG]
Q2  SSM3K35AMFV,L3F  [FP-SSM3K35AMFV,L3F_SOT-723-MFG]
R1  value 0  [FP-RC0402JR-070RP_0402-MFG]  (hidden comment: RC0402JR-070RP)
R2  ValueDisplayed: 40.2k  [0402L]  (hidden comment: CRCW040240K2FKED)
R3  value 0  [FP-RC0402JR-070RP_0402-MFG]  (hidden comment: RC0402JR-070RP)
R5  value 0  [FP-RC0402JR-070RP_0402-MFG]  (hidden comment: RC0402JR-070RP)
R7  value 0  [FP-RC0402JR-070RP_0402-MFG]  (hidden comment: RC0402JR-070RP)
R8  ValueDisplayed: 10.0k  [0402L]  (hidden comment: CRCW040210K0FKED)
R9  ValueDisplayed: 10.0k  [0402L]  (hidden comment: CRCW040210K0FKED)
R10  value 100k  [0402]  (hidden comment: CRCW0402100KFKED)
R23  value 100k  [0201L]  (hidden comment: CRCW0201100KFKED)
R26  ValueDisplayed: 1.00M  [0402]  (hidden comment: RC0402FR-071ML)
R27  value 18k  [FP-CRCW040218K0FKEDC_0402-MFG]  (hidden comment: CRCW040218K0FKEDC)
R28  ValueDisplayed: 510  [0402L]  (hidden comment: ERJ-2RKF5100X)
R29  ValueDisplayed: 510  [0402L]  (hidden comment: ERJ-2RKF5100X)
R172  ValueDisplayed: 510  [0402L]  (hidden comment: ERJ-2RKF5100X)
R175  value 100k  [0201L]  (hidden comment: CRCW0201100KFKED)
R176  Res_ohm: 0  [FP-RC0201JR-070RL_0201 (0603 Metric)-IPC_C]  (hidden comment: RC0201JR-070RL)
R179  ValueDisplayed: 510  [0402L]  (hidden comment: ERJ-2RKF5100X)
R180  value 18k  [FP-CRCW040218K0FKEDC_0402-MFG]  (hidden comment: CRCW040218K0FKEDC)
R244  ValueDisplayed: 1.00M  [0402]  (hidden comment: RC0402FR-071ML)
TP2  TESTPOINT  [TP_25MIL-SMT]  (value not drawn)  (no BOM)
TP4  TESTPOINT  [TP_25MIL-SMT]  (value not drawn)  (no BOM)
TP6  TESTPOINT  [TP_25MIL-SMT]  (value not drawn)  (no BOM)
TP9  TESTPOINT  [TP_25MIL-SMT]  (value not drawn)  (no BOM)
TP11  TESTPOINT  [TP_25MIL-SMT]  (value not drawn)  (no BOM)
U1  TPS2116DRLR  [DRL0008A-MFG]
U2  TPS6285021HQDRLRQ1  [DRL0008A-MFG]
U20  TPS6285020MDRLR  [DRL0008A-MFG]

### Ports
GPIO_4 (in), RADAR_NRST (bidir), REG_MODE_SELECT (bidir)

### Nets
5V_IN_USB: C25.1 C28.1 C45.1 R5.2 U2.1(VIN)
DC_OUT_3V3: C19.1 C49.1 C50.1 L2.2 L3.1 R23.1 R28.1 U2.5(FB)
GND: C1.2 C3.2 C4.2 C7.2 C8.1 C10.2 C11.2 C16.2 C19.2 C25.2 C28.2 C45.2 C49.2 C50.2 C56.2 C60.2 C69.2 C72.2 C73.2 C74.2 C128.2 C129.2 Q1.2(S) Q2.2(S) R2.1 R10.1 R26.2 R27.2 R180.2 R244.2 TP11.1 U1.1(GND) U2.8(GND) U20.8(GND)
OUT_3V3: C1.1 C3.1 R9.2 TP6.1 U1.3(VIN1) U1.5(MODE)
RADAR_3V3: R175.1 TP9.1
REG_1V8: C11.1 L6.2 TP2.1
REG_3V3: C4.1 C10.1 C56.1 C60.1 C69.1 C72.1 C73.1 C74.1 L4.2 R3.2 R8.1 R172.1 U20.1(VIN)
REG_OUT_1V8: C2.1 C128.1 C129.1 L6.1 L15.2 R1.2
USB_INPUT_3V3: C7.1 C8.2 C16.1 L3.2 U1.6(VIN2)
GPIO_4: R7.1 ; port GPIO_4
RADAR_NRST: R176.1 ; port RADAR_NRST
REG_MODE_SELECT: R7.2 R26.1 R244.1 TP4.1 U2.3(MODE) U20.3(MODE/SYNC) ; port REG_MODE_SELECT
REG_PG_1V8: R175.2 R176.2 R179.2 U20.6(PG)
REG_PG_3V3: R23.2 R29.2 U2.6(PG)
SW3_1V8: L15.1 U20.7(SW)
SW3_3V3: L2.1 U2.7(SW)
SW_PR1: R9.1 R10.2 U1.4(PR1)
SW_ST: R8.2 U1.8(ST)
NetC2_2: C2.2 R1.1 R2.2 U20.5(FB)
NetD2_1: D2.1(CATHODE) Q2.3(D)
NetD2_2: D2.2(ANODE) R28.2
NetD3_1: D3.1(CATHODE) Q1.3(D)
NetD3_2: D3.2(ANODE) R172.2
NetL4_1: L4.1 U1.2(VOUT) U1.7(VOUT)
NetQ1_1: Q1.1(G) R179.1
NetQ2_1: Q2.1(G) R29.1
NetR3_1: R3.1 U20.2(EN)
NetR5_1: R5.1 U2.2(EN)
NetR27_1: R27.1 U2.4(COMP/FSET)
NetR180_1: R180.1 U20.4(COMP/FSET)

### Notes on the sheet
- TEST POINTS
- DC-DC REGULATORS - 3.3V & 1.8V OUTPUTS
- PGOOD LED
- CAD NOTE : Place all Input & Output Decaps close to Regulator Pins - U[20]
- CAD NOTE : Place all Input & Output Decaps close to Regulator Pins - U[2]
- POWER MUX
- Mode : Priority Mode
- If VPR1 is high (VPR1 > VREF), then Vout = Vin1
- If VPR1 is low (VPR1 < VREF), then Vout = Vin2

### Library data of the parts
C1 C4 C7 = CMP-0006272-2: CAP, CERM, 1 uF, 10 V, +/- 10%, X6S, 0402; Manufacturer: TDK; Polarized: N; Value: 1uF; U/M: EA; Cap_F: 1µF; Value1: Unknown; VDC_V: 16V; TempCo: X5R; TaMin_C: -55°C; TaMax_C: 85°C; Cap_Case: 0402; SizeArea_mm2: 0.5; SizeAreaWB_mm2: 3; SizeX_mm: 1; SizeZ_mm: 0.6; AEC Category: Q200
C2 C19 = CMP-0006408-2: CAP, CERM, 10 pF, 50 V, +/- 5%, C0G/NP0, 0402; Manufacturer: MuRata; TaMin_C: -55°C; Polarized: N; SizeAreaWB_mm2: 3; Value1: Unknown; U/M: EA; Value: 10pF; TaMax_C: 125°C; SizeZ_mm: 0.6; SizeX_mm: 1; SizeY_mm: 0.5; Cap_Case: 0402; AEC Category: Q200
C3 C8 = CMP-0006356-2: CAP, CERM, 0.1 uF, 50 V, +/- 10%, X7R, AEC-Q200 Grade 1, 0402; Manufacturer: MuRata; AEC Qualified: Y; SizeZ_mm: 0.6; VDC_V: 50V; AEC Category: Q200; AEC Grade: 1; Polarized: N; SizeArea_mm2: 0.5; SizeAreaWB_mm2: 3; TaMax_C: 125°C; TaMin_C: -55°C; U/M: EA; Value1: Unknown; Value: 0.1uF
C10 = CMP-0006356-2: CAP, CERM, 0.1 uF, 50 V, +/- 10%, X7R, AEC-Q200 Grade 1, 0402; Manufacturer: MuRata; TaMin_C: -55°C; Polarized: N; SizeAreaWB_mm2: 3; Value1: Unknown; U/M: EA; Value: 0.1uF; TaMax_C: 125°C; SizeZ_mm: 0.6; SizeX_mm: 1; SizeY_mm: 0.5; Value2: 50V; AEC Qualified: Y; Cap_F: 100nF; AEC Category: Q200
C11 C16 = CMP-0078699-1: CAP, CERM, 47 µF, 10 V,+/- 20%, X5R, 0805; Manufacturer: MuRata; TaMin_C: -55°C; Polarized: N; Green_Lifecycle: Active; SizeAreaWB_mm2: 6.75; Green_REACh: Passed; U/M: EA; Value: 47uF; TaMax_C: 85°C; SizeZ_mm: 1.45; SizeX_mm: 2; SizeY_mm: 1.25; Cap_Case: 0805; SizeArea_mm2: 2.5; AEC Category: Q200
C25 C49 C50 C56 C72 C128 C129 = CMP-0007497-5: CAP, CERM, 10 uF, 10 V, +/- 20%, X7R, 0603; Manufacturer: MuRata; TaMin_C: -55°C; Polarized: N; SizeAreaWB_mm2: 4.68; Value1: Unknown; U/M: EA; Value: 10uF; TaMax_C: 125°C; SizeZ_mm: 1; SizeX_mm: 1.6; SizeY_mm: 0.8; Cap_Case: 0603; SizeArea_mm2: 1.28; AEC Category: Q200
C28 C60 C73 = CMP-0007398-4: CAP, CERM, 0.47 uF, 16 V, +/- 10%, X7R, 0603; Manufacturer: MuRata; TaMin_C: -55°C; Polarized: N; SizeAreaWB_mm2: 4.68; Value1: Unknown; U/M: EA; Value: 0.47uF; TaMax_C: 125°C; SizeZ_mm: 1; SizeX_mm: 1.6; SizeY_mm: 0.8; Cap_Case: 0603; SizeArea_mm2: 1.28; AEC Category: Q200
C45 C69 C74 = CMP-0006470-2: CAP, CERM, 470 pF, 50 V, +/- 5%, C0G/NP0, 0402; Manufacturer: MuRata; TaMin_C: -55°C; Polarized: N; SizeAreaWB_mm2: 3; Value1: Unknown; U/M: EA; Value: 470pF; TaMax_C: 125°C; SizeZ_mm: 0.6; SizeX_mm: 1; SizeY_mm: 0.5; Cap_Case: 0402; AEC Category: Q200
D2 D3 = CMP-0090807-1: LED Uni-Color Yellow 588nm 2-Pin Chip 0402(1006Metric) T/R; Manufacturer: Vishay; AEC Qualified: No; Led Orientation: Top View; SizeZ_mm: 0.35mm; TaMin_C: -30°C; Angle: 130°; LambdaD: 590nm; Power_TotalModule: 75mW; TaMax_C: +85°C; Forward Current: 20mA; Vr_V: 5V; Vf_V: 2V; Luminous Intensity: 90mcd
L2 L15 = CMP-0092096-1: 470nH Shielded Wirewound Inductor 3A 42mOhm Max 0805 (2012 Metric); Manufacturer: Murata; DCR_ohm: 42m; Shrouded: true; SizeZ_mm: 1mm; Value: 0.47uH; Tolerance_%: 20%; Test Frequency: 1MHz; Isat: 4.4A; AEC Qualified: No; Material: Metal Alloy
L3 L6 = CMP-0124620-1: 100 nH Shielded Drum Core, Wirewound Inductor 3.65 A 22mOhm Max 0806 (2016 Metric); Manufacturer: Sunlord; AEC Qualified: No; DCR_ohm: 22m; Irms: 4.25A; Isat: 4.8A; Material: Ferrite; SizeZ_mm: 1mm; Value: 0.1uH; Self Resonant Frequency: 583MHz; Shrouded: true; Test Frequency: 1MHz; Tolerance_%: 20%
L4 = CMP-0077879-2: Ferrite Bead, 120 ohm @ 100 MHz, 1.9 A, 0603; Manufacturer: MuRata; ZTyp@100MHz_Ohm: 120; SizeAreaWB_mm2: 4.68; DCR_ohm: 0.04; Value1: 0.04 ohm; Value: 120 ohm; Imax_A: 1.9A; SizeZ_mm: 1.0; SizeX_mm: 1.6; SizeY_mm: 0.8; SizeArea_mm2: 1.28
Q1 Q2 = CMP-0091833-1: N-Channel 20V 250mA (Ta) 500mW (Ta) Surface Mount VESM; Manufacturer: Toshiba; Threshold Vgs Min: 0.35V; QgTyp_nC: 0.34nC @ 4.5V; AEC Qualified: No; Rdson45_ohm: 0.75; TJmax_C: +150°C; Input Capacitace At Vds: 18pF @ 10V; SizeZ_mm: 0.55mm; Pulse Drain Current: 600mA; Threshold Vgs Max: 1V; Vgs_V: 10V; Typ Forward Diode Voltage: 0.8V; VdsMax_V: 1.2V; Power_W: 150mW; Number Of N Channels: 1; Turn Off Delay Time: 6.5ns; ChMode: False; Turn On Delay Time: 2ns
R1 R3 R5 R7 = CMP-0093147-1: as R12 on sheet TIDA-010967_USB_PWR_Connector
R2 = CMP-0026367-2: RES, 40.2 k, 1%, 0.063 W, AEC-Q200 Grade 0, 0402; Manufacturer: Vishay-Dale; Power_W: 63mW; TempCo: 100 ppm/C; Value_Code: 40k2; Value: 40.2k; EIA_Code: E96; SizeX_mm: 1; SizeY_mm: 0.5; SizeZ_mm: 0.6; Value2: 0.063W; AEC Qualified: Y; VDC_V: 50V; AEC Category: Q200; AEC Grade: 0
R8 R9 = CMP-0025958-3: as R16 on sheet TIDA-010967_USB_PWR_Connector
R10 = CMP-0025950-3: RES, 100 k, 1%, 0.063 W, AEC-Q200 Grade 0, 0402; Manufacturer: Vishay-Dale; AEC Category: Q200; AEC Grade: 0; AEC Qualified: Y; EIA_Code: E96; Power_W: 63mW; SizeArea_mm2: 0.5; SizeX_mm: 1; SizeZ_mm: 0.6; TempCo: 100 ppm/C; Value2: 0.063W; VDC_V: 50V
R23 R175 = CMP-0027261-3: RES, 100 k, 1%, 0.05 W, 0201; Manufacturer: Vishay-Dale; AEC Category: Q200; AEC Qualified: N; EIA_Code: E96; Power_W: 50mW; SizeArea_mm2: 0.18; SizeX_mm: 0.6; SizeY_mm: 0.3; SizeZ_mm: 0.26; TempCo: 100 ppm/C; Value2: 0.05W; VDC_V: 30V
R26 R244 = CMP-0026727-1: RES, 1.00 M, 1%, 0.063 W, 0402; Manufacturer: Yageo America; Power_W: 63mW; TempCo: 100 ppm/C; Value_Code: 1M00; U/M: EA; Value: 1.00Meg; EIA_Code: E96; Res_ohm: 1M; SizeX_mm: 1; SizeY_mm: 0.5; SizeZ_mm: 0.6; Value2: 0.063W; AEC Category: Q200
R27 R180 = CMP-0094741-1: Res Thick Film 0402 18K Ohm 1% 1/16W ±100ppm/°C Molded SMD Paper T/R; Manufacturer: Vishay; VDC_V: 50V; SizeZ_mm: 0.35mm; AEC Qualified: No; Power_W: 63mW
R28 R29 R172 R179 = CMP-0026704-1: RES, 510, 1%, 0.1 W, 0402; Manufacturer: Panasonic; Power_W: 100mW; TempCo: 100 ppm/C; Value_Code: 510R; U/M: EA; Value: 510; SizeX_mm: 1; SizeY_mm: 0.5; SizeZ_mm: 0.6; Value2: 0.1W; VDC_V: 50V; AEC Category: Q200
R176 = CMP-0086442-2: RES SMD 0 OHM JUMPER 1/20W 0201; Manufacturer: Yageo; AEC Qualified: No; Power_W: 50mW; SizeZ_mm: 0.26mm; TempCo: 200ppm/°C; Tolerance_%: 5%; VDC_V: 25V
TP2 TP4 TP6 TP9 TP11 = CMP-0078143-4: TEST POINT.  No entry in BOM.
U1 = CMP-0088593-2: 1.6 V to 5 V, 2.5-A Low IQ Power Mux With Manual and Automatic Switchover; Manufacturer: Texas Instruments; Max Supply Voltage: 5.5V; TaMax_C: +125°C; Output Voltage: 0-5.5V; CompType: IC; Min Supply Voltage: 1.6V; TaMin_C: -55°C; SizeZ_mm: 0.6mm; AEC Category: Q200; Nominal Supply Current: 0.5-1uA; Number Of Outputs: 1; Standoff Height: 0mm; AEC Qualified: No
U2 = CMP-0092337-2: 2.7-V to 6-V, 2-A Automotive Step-Down Converter in SOT583 Package; Manufacturer: Texas Instruments; AEC Qualified: Yes; Nominal Supply Current: 17uA; Output Type: AdjustableProgrammable; AEC Category: Q200; Number Of Outputs: 1; Switching Frequency: 1.8-4MHz; TaMax_C: +125°C; Max Supply Voltage: 6V; Min Supply Voltage: 2.7V; SizeZ_mm: 0.6mm; Standoff Height: 0mm; AEC Grade: Grade 1; TJmax_C: +150°C; Switching Topology: Buck; Max Duty Cycle: 100%; TaMin_C: -40°C; CompType: IC; Output Voltage: 0.6-5.5V
U20 = CMP-0120069-1: 2.7-V to 6-V, 2-A Step-Down Converter in SOT583 Package; Manufacturer: Texas Instruments; SizeZ_mm: 0.6mm; AEC Qualified: No; Max Duty Cycle: 100%; Max Supply Voltage: 6V; Min Supply Voltage: 2.7V; Nominal Supply Current: 17uA; Number Of Outputs: 1; Output Type: AdjustableProgrammable; Output Voltage: 0.6-5.5V; Standoff Height: 0mm; Switching Frequency: 1.8-4MHz; Switching Topology: Buck; TJmax_C: +150°C

## Sheet TIDA-010967_xWRL6432_Chip.SchDoc: xWRL6432AOP_CHIP
size 431 x 279 mm; Date: Not shown in title block; ApprovedBy: Not shown in title block; CheckedBy: Not shown in title block; Author: Not shown in title block; CompanyName: Not shown in title block; DrawnBy: Justin Yin; Engineer: Not shown in title block; Organization: Not shown in title block; Address1: Not shown in title block; Address2: Not shown in title block; Address3: Not shown in title block; Address4: Not shown in title block; DocumentNumber: 5; Revision: Use project parameter SCH_Rev; SheetNumber: 5; SheetTotal: 8; PageSetup: Record=PageOptions¦CenterHorizontal=True¦CenterVertical=True¦PrintScale=1.00¦XCorrection=1.00¦YCorrection=1.00¦PrintKind=0¦BorderSize=5000000¦LeftOffset=0¦BottomOffset=0¦Orientation=2¦PaperLength=1000¦PaperWidth=1000¦Scale=100¦PaperSource=15¦PrintQuality=600¦MediaType=1¦DitherType=10¦PaperKind=Letter¦PrintScaleMode=1
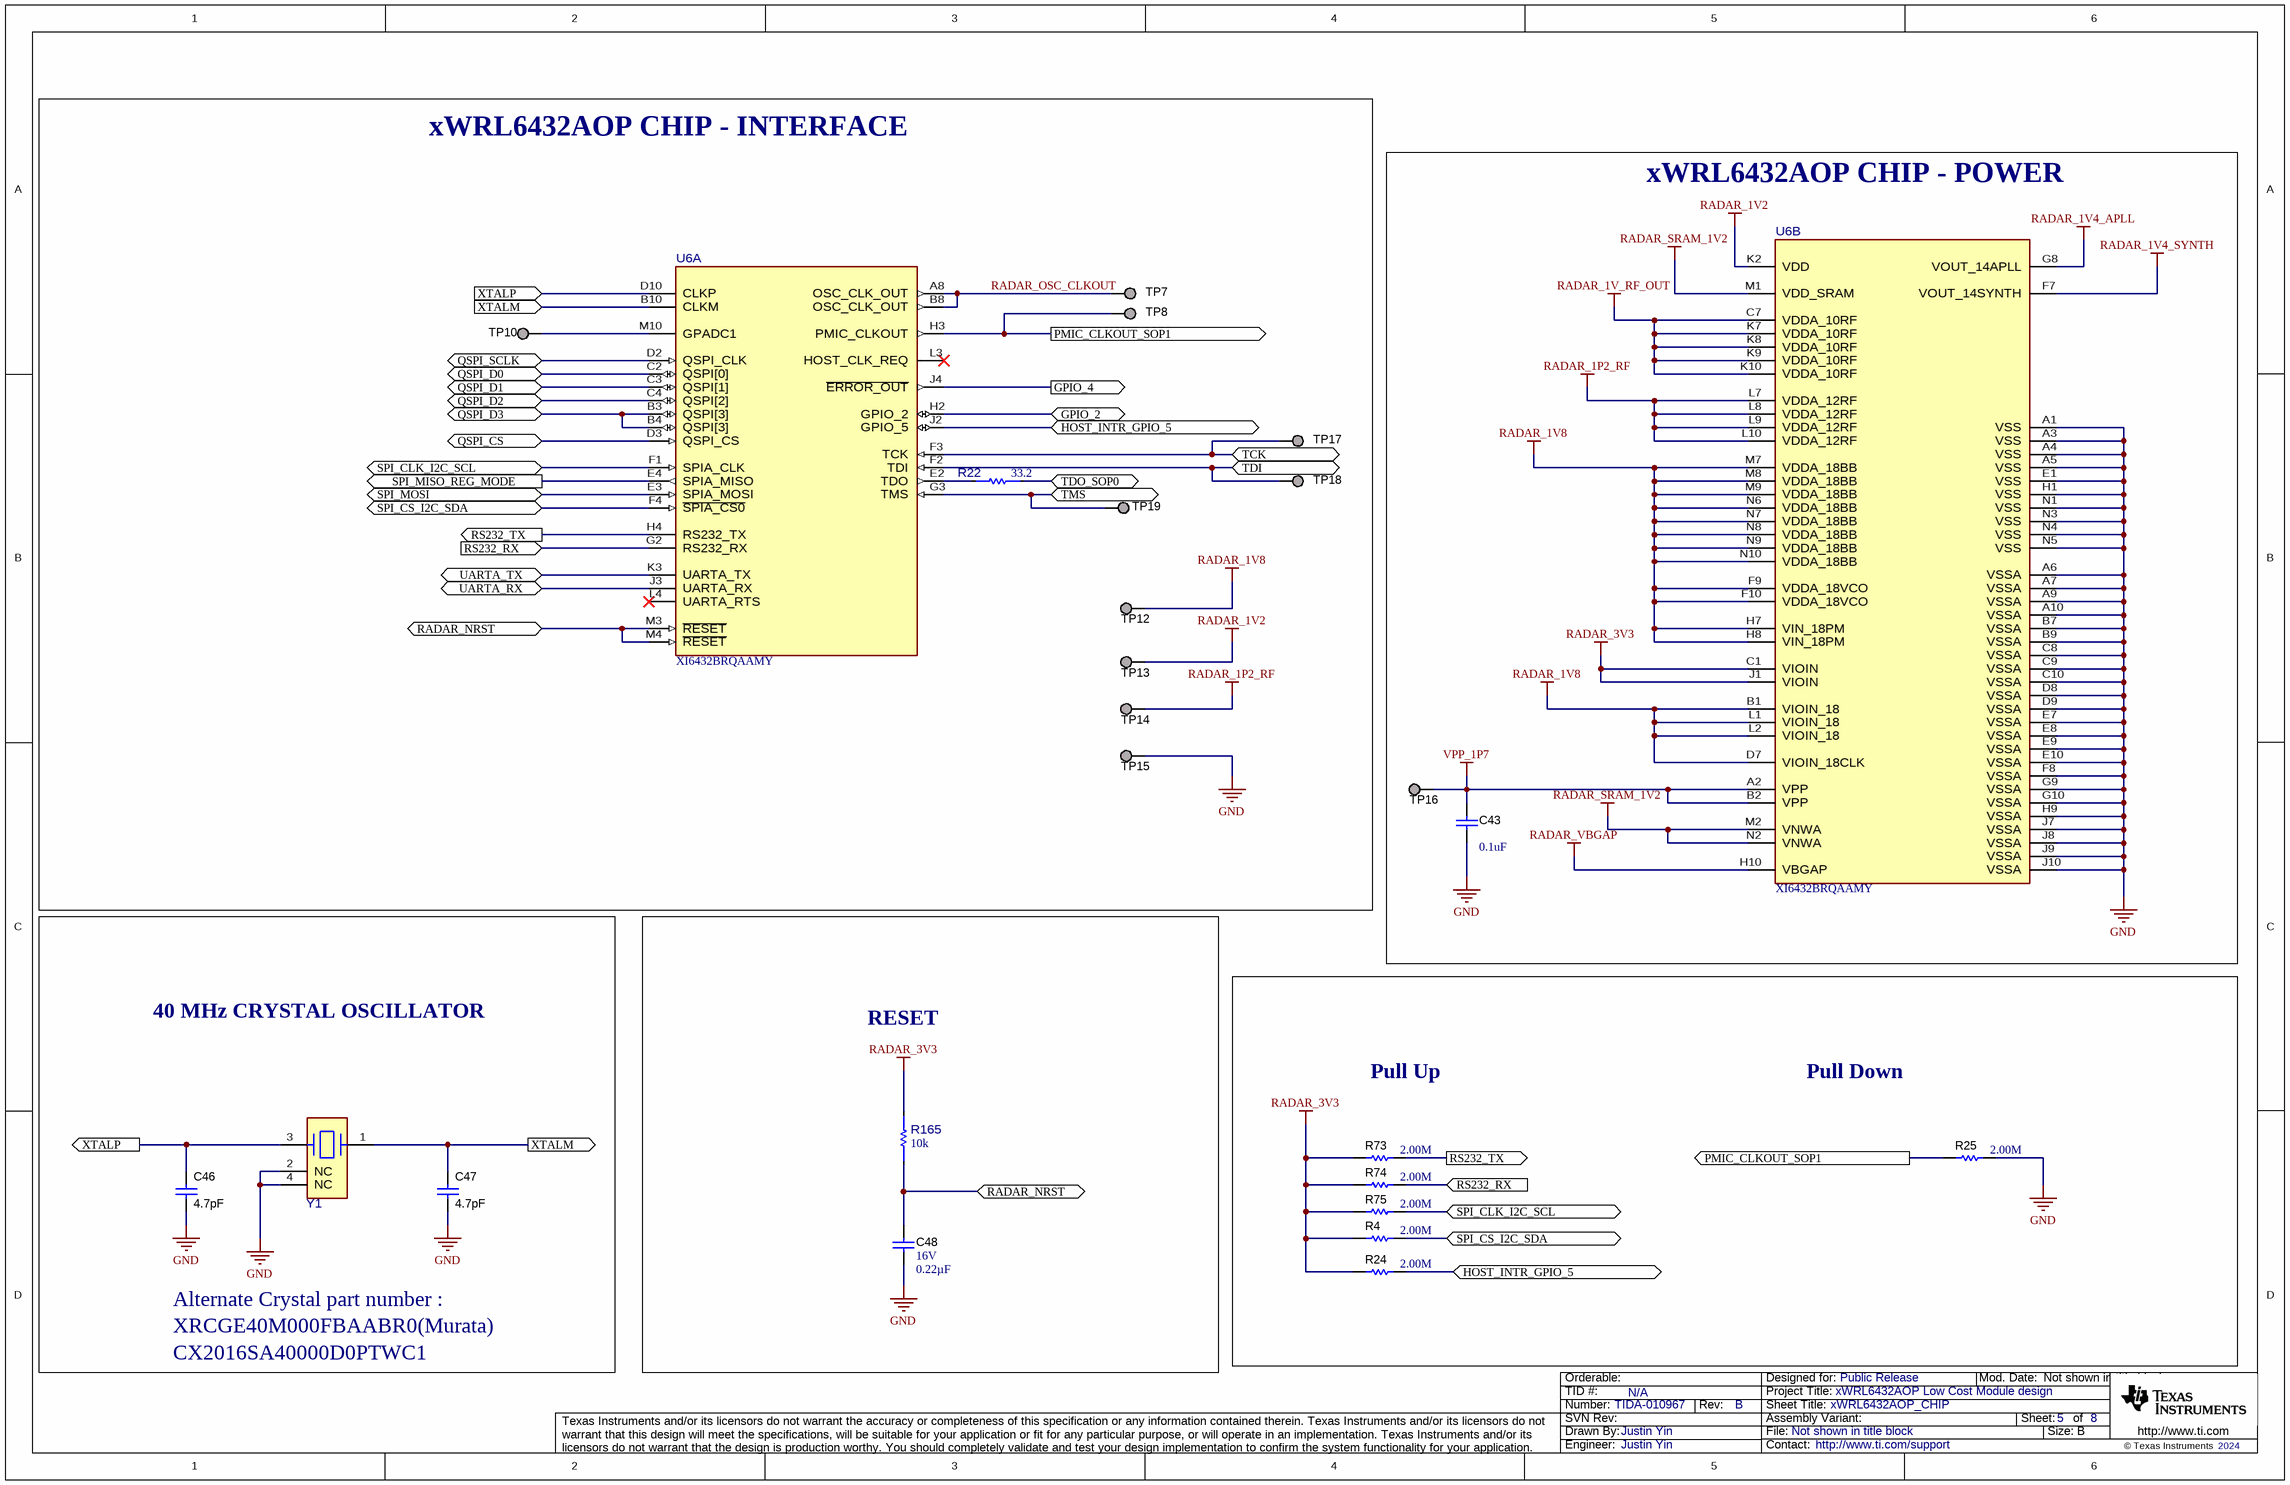
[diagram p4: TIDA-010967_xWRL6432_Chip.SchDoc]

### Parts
C43  ValueDisplayed: 0.1uF  [0402]  (hidden comment: C1005X7R1H104K050BE)
C46  ValueDisplayed: 4.7pF  [0402L]  (hidden comment: GJM1555C1H4R7BB01D)
C47  ValueDisplayed: 4.7pF  [0402L]  (hidden comment: GJM1555C1H4R7BB01D)
C48  VDC_V: 16V  ValueDisplayed: 0.22µF  [0402L]  (hidden comment: CL05B224KO5NNNC)
R4  ValueDisplayed: 2.00M  [0402]  (hidden comment: CRCW04022M00FKED)
R22  value 33.2  [FP-RT0402FRE0733R2L_0402-MFG]  (hidden comment: RT0402FRE0733R2L)
R24  ValueDisplayed: 2.00M  [0402]  (hidden comment: CRCW04022M00FKED)
R25  ValueDisplayed: 2.00M  [0402]  (hidden comment: CRCW04022M00FKED)
R73  ValueDisplayed: 2.00M  [0402]  (hidden comment: CRCW04022M00FKED)
R74  ValueDisplayed: 2.00M  [0402]  (hidden comment: CRCW04022M00FKED)
R75  ValueDisplayed: 2.00M  [0402]  (hidden comment: CRCW04022M00FKED)
R165  Res_ohm: 10k  [FP-ERJ-1RHD1002C_0201-MFG]  (hidden comment: ERJ-1RHD1002C)
TP7  TESTPOINT  [TP_25MIL-SMT]  (value not drawn)  (no BOM)
TP8  TESTPOINT  [TP_25MIL-SMT]  (value not drawn)  (no BOM)
TP10  TESTPOINT  [TP_25MIL-SMT]  (value not drawn)  (no BOM)
TP12  TESTPOINT  [TP_25MIL-SMT]  (value not drawn)  (no BOM)
TP13  TESTPOINT  [TP_25MIL-SMT]  (value not drawn)  (no BOM)
TP14  TESTPOINT  [TP_25MIL-SMT]  (value not drawn)  (no BOM)
TP15  TESTPOINT  [TP_25MIL-SMT]  (value not drawn)  (no BOM)
TP16  TESTPOINT  [TP_25MIL-SMT]  (value not drawn)  (no BOM)
TP17  TESTPOINT  [TP_25MIL-SMT]  (value not drawn)  (no BOM)
TP18  TESTPOINT  [TP_25MIL-SMT]  (value not drawn)  (no BOM)
TP19  TESTPOINT  [TP_25MIL-SMT]  (value not drawn)  (no BOM)
U6  XI6432BRQAAMY  [AMY0101A-MFG]  (parts A,B of 2)
Y1  XRCGB40M000F1S2GR0  [FP-XRCGB40M000F1S2GR0_SMT_CRYSTAL_2MM0_1MM6-MFG]  (value not drawn)

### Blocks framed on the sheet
xWRL6432AOP CHIP - INTERFACE: R22 TP7 TP8 TP10 TP12-TP15 TP17-TP19 U6
xWRL6432AOP CHIP - POWER: C43 TP16 U6
RESET: C48 R165

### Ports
GPIO_2 (bidir), GPIO_4 (out), HOST_INTR_GPIO_5 (bidir), PMIC_CLKOUT_SOP1 (out), QSPI_CS (bidir), QSPI_D0 (bidir), QSPI_D1 (bidir), QSPI_D2 (bidir), QSPI_D3 (bidir), QSPI_SCLK (bidir), RADAR_NRST (bidir), RS232_RX (in), RS232_TX (out), SPI_CLK_I2C_SCL (bidir), SPI_CS_I2C_SDA (bidir), SPI_MISO_REG_MODE (out), SPI_MOSI (bidir), TCK (bidir), TDI (bidir), TDO_SOP0 (bidir), TMS (bidir), UARTA_RX (bidir), UARTA_TX (bidir), XTALM (in), XTALM (out), XTALP (in), XTALP (out)

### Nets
GND: C43.2 C46.1 C47.1 C48.1 R25.2 TP15.1 U6.A1(VSS) U6.A3(VSS) U6.A4(VSS) U6.A5(VSS) U6.A6(VSSA) U6.A7(VSSA) U6.A9(VSSA) U6.A10(VSSA) U6.B7(VSSA) U6.B9(VSSA) U6.C8(VSSA) U6.C9(VSSA) U6.C10(VSSA) U6.D8(VSSA) U6.D9(VSSA) U6.E1(VSS) U6.E7(VSSA) U6.E8(VSSA) U6.E9(VSSA) U6.E10(VSSA) U6.F8(VSSA) U6.G9(VSSA) U6.G10(VSSA) U6.H1(VSS) U6.H9(VSSA) U6.J7(VSSA) U6.J8(VSSA) U6.J9(VSSA) U6.J10(VSSA) U6.N1(VSS) U6.N3(VSS) U6.N4(VSS) U6.N5(VSS) Y1.2(NC) Y1.4(NC)
RADAR_1P2_RF: TP14.1 U6.L7(VDDA_12RF) U6.L8(VDDA_12RF) U6.L9(VDDA_12RF) U6.L10(VDDA_12RF)
RADAR_1V2: TP13.1 U6.K2(VDD)
RADAR_1V4_APLL: U6.G8(VOUT_14APLL)
RADAR_1V4_SYNTH: U6.F7(VOUT_14SYNTH)
RADAR_1V8: TP12.1 U6.B1(VIOIN_18) U6.D7(VIOIN_18CLK) U6.F9(VDDA_18VCO) U6.F10(VDDA_18VCO) U6.H7(VIN_18PM) U6.H8(VIN_18PM) U6.L1(VIOIN_18) U6.L2(VIOIN_18) U6.M7(VDDA_18BB) U6.M8(VDDA_18BB) U6.M9(VDDA_18BB) U6.N6(VDDA_18BB) U6.N7(VDDA_18BB) U6.N8(VDDA_18BB) U6.N9(VDDA_18BB) U6.N10(VDDA_18BB)
RADAR_1V_RF_OUT: U6.C7(VDDA_10RF) U6.K7(VDDA_10RF) U6.K8(VDDA_10RF) U6.K9(VDDA_10RF) U6.K10(VDDA_10RF)
RADAR_3V3: R4.1 R24.1 R73.1 R74.1 R75.1 R165.2 U6.C1(VIOIN) U6.J1(VIOIN)
RADAR_SRAM_1V2: U6.M1(VDD_SRAM) U6.M2(VNWA) U6.N2(VNWA)
RADAR_VBGAP: U6.H10(VBGAP)
VPP_1P7: C43.1 TP16.1 U6.A2(VPP) U6.B2(VPP)
GPIO_2: U6.H2(GPIO_2) ; port GPIO_2
GPIO_4: U6.J4(~{ERROR_OUT}) ; port GPIO_4
HOST_INTR_GPIO_5: R24.2 U6.J2(GPIO_5) ; port HOST_INTR_GPIO_5
PMIC_CLKOUT_SOP1: R25.1 TP8.1 U6.H3(PMIC_CLKOUT) ; port PMIC_CLKOUT_SOP1
QSPI_CS: U6.D3(QSPI_CS) ; port QSPI_CS
QSPI_D0: U6.C2(QSPI[0]) ; port QSPI_D0
QSPI_D1: U6.C3(QSPI[1]) ; port QSPI_D1
QSPI_D2: U6.C4(QSPI[2]) ; port QSPI_D2
QSPI_D3: U6.B3(QSPI[3]) U6.B4(QSPI[3]) ; port QSPI_D3
QSPI_SCLK: U6.D2(QSPI_CLK) ; port QSPI_SCLK
RADAR_NRST: C48.2 R165.1 U6.M3(~{RESET}) U6.M4(~{RESET}) ; port RADAR_NRST
RADAR_OSC_CLKOUT: TP7.1 U6.A8(OSC_CLK_OUT) U6.B8(OSC_CLK_OUT)
RS232_RX: R74.2 U6.G2(RS232_RX) ; port RS232_RX
RS232_TX: R73.2 U6.H4(RS232_TX) ; port RS232_TX
SPI_CLK_I2C_SCL: R75.2 U6.F1(SPIA_CLK) ; port SPI_CLK_I2C_SCL
SPI_CS_I2C_SDA: R4.2 U6.F4(~{SPIA_CS0}) ; port SPI_CS_I2C_SDA
SPI_MISO_REG_MODE: U6.E4(SPIA_MISO) ; port SPI_MISO_REG_MODE
SPI_MOSI: U6.E3(SPIA_MOSI) ; port SPI_MOSI
TCK: TP17.1 U6.F3(TCK) ; port TCK
TDI: TP18.1 U6.F2(TDI) ; port TDI
TDO_SOP0: R22.1 ; port TDO_SOP0
TMS: TP19.1 U6.G3(TMS) ; port TMS
UARTA_RX: U6.J3(UARTA_RX) ; port UARTA_RX
UARTA_TX: U6.K3(UARTA_TX) ; port UARTA_TX
XTALM: C47.2 U6.B10(CLKM) Y1.1 ; port XTALM
XTALP: C46.2 U6.D10(CLKP) Y1.3 ; port XTALP
NetR22_2: R22.2 U6.E2(TDO)
NetTP10_1: TP10.1 U6.M10(GPADC1)

Not connected (* = marked no-connect by the designer): U6 L3(HOST_CLK_REQ)* L4(UARTA_RTS)*

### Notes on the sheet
- 40 MHz CRYSTAL OSCILLATOR
- Pull Up
- Pull Down
- Alternate Crystal part number :
- XRCGE40M000FBAABR0(Murata)
- CX2016SA40000D0PTWC1

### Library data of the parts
C43 = CMP-0064946-2: CAP, CERM, 0.1 uF, 50 V,+/- 10%, X7R, 0402; Manufacturer: TDK; TaMin_C: -55°C; Polarized: N; SizeAreaWB_mm2: 3; Value1: Unknown; U/M: EA; Value: 0.1uF; TaMax_C: 125°C; SizeZ_mm: 0.6; SizeX_mm: 1; SizeY_mm: 0.5; Value2: 50V; Cap_F: 100nF; AEC Category: Q200
C46 C47 = CMP-0006367-2: CAP, CERM, 4.7 pF, 50 V, +/- 2%, C0G/NP0, 0402; Manufacturer: MuRata; TaMin_C: -55°C; Polarized: N; SizeAreaWB_mm2: 3; Value1: Unknown; U/M: EA; Value: 4.7pF; TaMax_C: 125°C; SizeZ_mm: 0.6; SizeX_mm: 1; SizeY_mm: 0.5; Cap_Case: 0402; Value2: 50V; CompType: Capacitor; AEC Category: Q200
C48 = CMP-0860563-1: CAP, CERM, 0.22 µF, 16 V,+/- 10%, X7R, 0402; Manufacturer: Samsung Electro-Mechanics; SizeX_mm: 1; Cap_Case: 0402; Green_REACh: Incomplete; TaMin_C: -55°C; SizeArea_mm2: 0.5; TaMax_C: 125°C; U/M: EA; Green_Lifecycle: Active; SizeAreaWB_mm2: 3; AEC Qualified: N; SizeZ_mm: 0.6; AEC Category: Q200; Cap_F: 220nF; Value: 0.22uF
R4 R24 R25 R73-R75 = CMP-0026245-2: RES, 2.00 M, 1%, 0.063 W, AEC-Q200 Grade 0, 0402; Manufacturer: Vishay-Dale; Power_W: 63mW; TempCo: 100 ppm/C; Value_Code: 2M00; Value: 2.00Meg; EIA_Code: E96; Res_ohm: 2M; SizeX_mm: 1; SizeY_mm: 0.5; SizeZ_mm: 0.6; Value2: 0.063W; AEC Qualified: Y; VDC_V: 50V; AEC Category: Q200; AEC Grade: 0
R22 = CMP-0120016-1: 33.2 Ohms ±1% 0.063W, 1/16W Chip Resistor 0402 (1005 Metric) Thin Film; Manufacturer: Yageo; AEC Qualified: No; Power_W: 63mW; SizeZ_mm: 0.35mm; TempCo: 50ppm/°C; VDC_V: 50V
R165 = CMP-0095015-1: Res Thick Film 0201 10K Ohm 0.5% 0.05W ±50ppm/°C Molded SMD Pressed Carrier T/R; Manufacturer: Panasonic; SizeZ_mm: 0.26mm; AEC Qualified: No; VDC_V: 15V; Power_W: 50mW
TP7 TP8 TP10 TP12-TP19 = CMP-0078143-4: TEST POINT.  No entry in BOM.
U6 = CMP-0120794-2: Manufacturer: Texas Instruments; SizeZ_mm: 0.757mm; Standoff Height: 0.219mm; AEC Category: Q200; CompType: IC
Y1 = CMP-0120019-1: Crystal Resonator 40MHz ±10ppm (Tol) ±20ppm (Stability) 8pF 50Ohm 4-Pin SMD T/R; Manufacturer: Murata; SizeZ_mm: 0.7mm; AEC Qualified: No; Esr: 50

## Sheet TIDA-010967_Decoupling_caps.SchDoc: DECOUPLING_CAPS
size 431 x 279 mm; Date: Not shown in title block; ApprovedBy: Not shown in title block; CheckedBy: Not shown in title block; Author: Not shown in title block; CompanyName: Not shown in title block; DrawnBy: Justin Yin; Engineer: Not shown in title block; Organization: Not shown in title block; Address1: Not shown in title block; Address2: Not shown in title block; Address3: Not shown in title block; Address4: Not shown in title block; DocumentNumber: 6; Revision: Use project parameter SCH_Rev; SheetNumber: 6; SheetTotal: 8; PageSetup: Record=PageOptions¦CenterHorizontal=True¦CenterVertical=True¦PrintScale=1.00¦XCorrection=1.00¦YCorrection=1.00¦PrintKind=0¦BorderSize=5000000¦LeftOffset=0¦BottomOffset=0¦Orientation=2¦PaperLength=1000¦PaperWidth=1000¦Scale=100¦PaperSource=15¦PrintQuality=600¦MediaType=1¦DitherType=10¦PaperKind=Letter¦PrintScaleMode=1
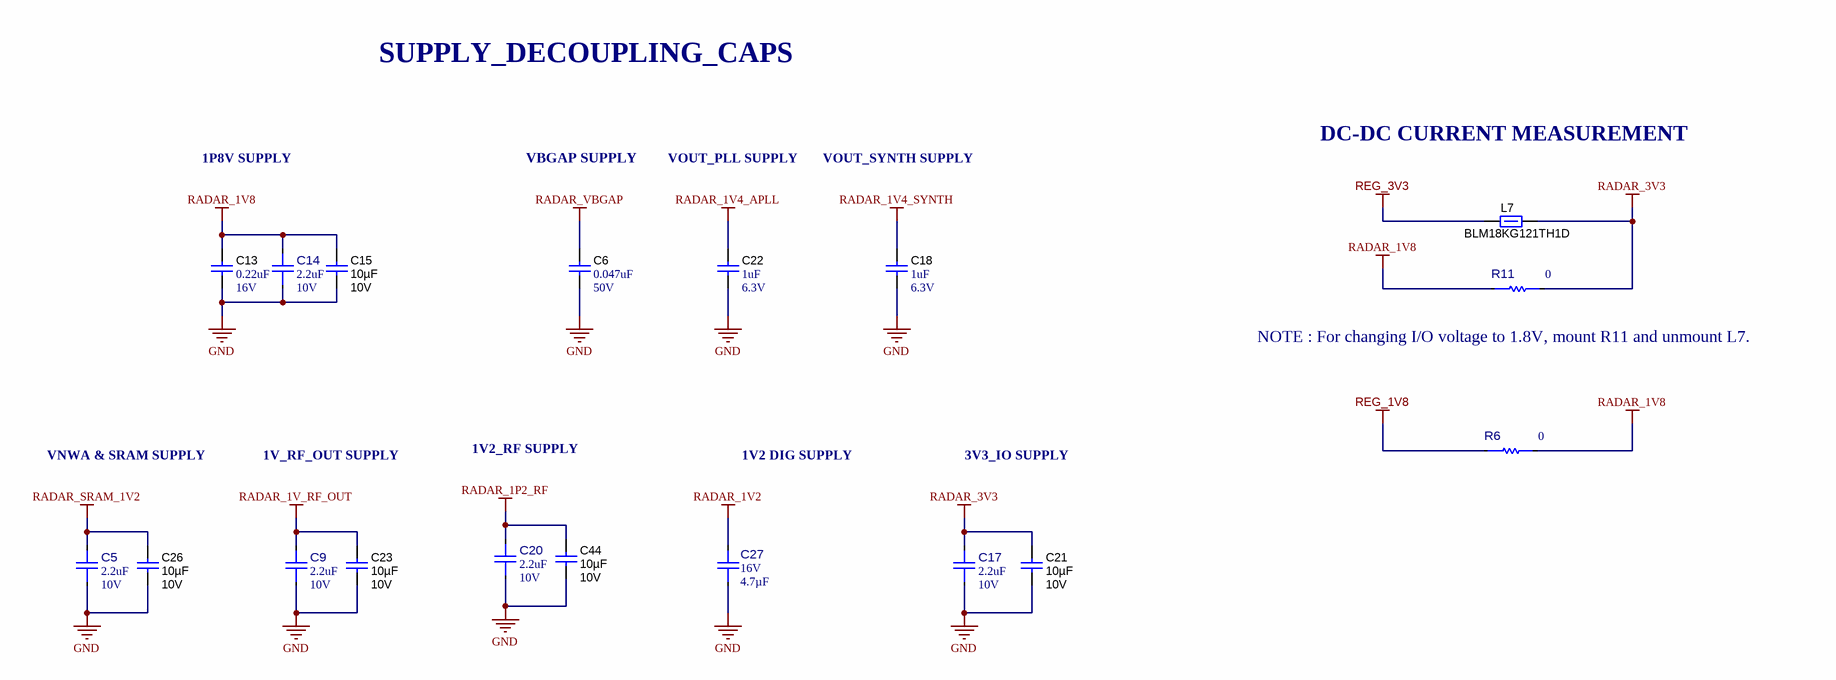
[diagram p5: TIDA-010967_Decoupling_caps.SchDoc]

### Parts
C5  ValueDisplayed: 2.2uF  VDC_V: 10V  [FP-GRM155R61A225ME01D_0402-MFG]  (hidden comment: GRM155R61A225ME01D)
C6  VDC_V: 50V  ValueDisplayed: 0.047uF  [0402L]  (hidden comment: C1005X7R1H473K050BB)
C9  ValueDisplayed: 2.2uF  VDC_V: 10V  [FP-GRM155R61A225ME01D_0402-MFG]  (hidden comment: GRM155R61A225ME01D)
C13  VDC_V: 16V  ValueDisplayed: 0.22uF  [0402L]  (hidden comment: GRM155R71C224KA12D)
C14  ValueDisplayed: 2.2uF  VDC_V: 10V  [FP-GRM155R61A225ME01D_0402-MFG]  (hidden comment: GRM155R61A225ME01D)
C15  Value2: 10V  Cap_F: 10µF  [0603L]  (hidden comment: GRM188Z71A106MA73D)
C17  ValueDisplayed: 2.2uF  VDC_V: 10V  [FP-GRM155R61A225ME01D_0402-MFG]  (hidden comment: GRM155R61A225ME01D)
C18  VDC_V: 6.3V  ValueDisplayed: 1uF  [0402S]  (hidden comment: GRM155R70J105KA12D)
C20  ValueDisplayed: 2.2uF  VDC_V: 10V  [FP-GRM155R61A225ME01D_0402-MFG]  (hidden comment: GRM155R61A225ME01D)
C21  Value2: 10V  Cap_F: 10µF  [0603L]  (hidden comment: GRM188Z71A106MA73D)
C22  VDC_V: 6.3V  ValueDisplayed: 1uF  [0402S]  (hidden comment: GRM155R70J105KA12D)
C23  Value2: 10V  Cap_F: 10µF  [0603L]  (hidden comment: GRM188Z71A106MA73D)
C26  Value2: 10V  Cap_F: 10µF  [0603L]  (hidden comment: GRM188Z71A106MA73D)
C27  VDC_V: 16V  Cap_F: 4.7µF  [FP-GCJ21BR71C475KA01L_0805-MFG]  (hidden comment: GCJ21BR71C475KA01L)
C44  Value2: 10V  Cap_F: 10µF  [0603L]  (hidden comment: GRM188Z71A106MA73D)
L7  BLM18KG121TH1D  [0603L]
R6  Res_ohm: 0  [FP-ERJ-3GEY0R00V_0603-MFG]  (hidden comment: ERJ-3GEY0R00V)
R11  Res_ohm: 0  [FP-ERJ-3GEY0R00V_0603-MFG]  (hidden comment: ERJ-3GEY0R00V)

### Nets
GND: C5.1 C6.2 C9.1 C13.2 C14.1 C15.2 C17.1 C18.2 C20.1 C21.2 C22.2 C23.2 C26.2 C27.1 C44.2
RADAR_1P2_RF: C20.2 C44.1
RADAR_1V2: C27.2
RADAR_1V4_APLL: C22.1
RADAR_1V4_SYNTH: C18.1
RADAR_1V8: C13.1 C14.2 C15.1 R6.2 R11.1
RADAR_1V_RF_OUT: C9.2 C23.1
RADAR_3V3: C17.2 C21.1 L7.2 R11.2
RADAR_SRAM_1V2: C5.2 C26.1
RADAR_VBGAP: C6.1
REG_1V8: R6.1
REG_3V3: L7.1

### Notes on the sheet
- SUPPLY_DECOUPLING_CAPS
- DC-DC CURRENT MEASUREMENT
- 1P8V SUPPLY
- VBGAP SUPPLY
- VOUT_PLL SUPPLY
- VOUT_SYNTH SUPPLY
- (near R11) NOTE : For changing I/O voltage to 1.8V, mount R11 and unmount L7.
- VNWA & SRAM SUPPLY
- 1V_RF_OUT SUPPLY
- 1V2_RF SUPPLY
- 1V2 DIG SUPPLY
- 3V3_IO SUPPLY

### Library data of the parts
C5 C9 C14 C17 C20 = CMP-0097887-1: Chip Multilayer Ceramic Capacitors for General Purpose, 0402, 2.2uF, X5R, 15%, 20%, 10V; Manufacturer: Murata; SizeZ_mm: 0.55mm; Value: 2.2µF; AEC Qualified: No
C6 = CMP-0006298-2: CAP, CERM, 0.047 uF, 50 V, +/- 10%, X7R, 0402; Manufacturer: TDK; TaMin_C: -55°C; ESR_ohm: 0.06407; Polarized: N; SizeAreaWB_mm2: 3; Value1: 0.06407 ohm; U/M: EA; SizeZ_mm: 0.6; SizeX_mm: 1; SizeY_mm: 0.5; Cap_Case: 0402; Cap_F: 47nF; IRMS_A: 6.46122dA; AEC Category: Q200; TaMax_C: 125°C
C13 = CMP-0006648-2: CAP, CERM, 0.22 uF, 16 V, +/- 10%, X7R, 0402; Manufacturer: MuRata; TaMin_C: -55°C; Polarized: N; SizeAreaWB_mm2: 3; Value1: Unknown; U/M: EA; Value: 0.22uF; TaMax_C: 125°C; SizeZ_mm: 0.6; SizeX_mm: 1; SizeY_mm: 0.5; Cap_Case: 0402; Cap_F: 220nF; AEC Category: Q200
C15 C21 C23 C26 C44 = CMP-0007497-5: as C25 on sheet TIDA-010967_DC_Regulators
C18 C22 = CMP-0064947-2: CAP, CERM, 1 uF, 6.3 V,+/- 10%, X7R, 0402; Manufacturer: MuRata; TaMin_C: -55°C; Polarized: N; SizeAreaWB_mm2: 3; Value1: Unknown; U/M: EA; Value: 1uF; TaMax_C: 125°C; SizeZ_mm: 0.6; SizeX_mm: 1; SizeY_mm: 0.5; Cap_Case: 0402; Cap_F: 1µF; AEC Category: Q200
C27 = CMP-0094778-1: Multilayer Ceramic Capacitors MLCC - SMD/SMT 0805 4.7uF 10%, 16VDC,  X7R 15%; Manufacturer: Murata; AEC Qualified: Yes; Value: 4.7µF; AEC Grade: Grade 1; SizeZ_mm: 1.45mm
L7 = CMP-0077879-2: as L4 on sheet TIDA-010967_DC_Regulators
R6 R11 = CMP-0089143-1: 0 Ohms Jumper 0.1W, 1/10W Chip Resistor 0603 (1608 Metric) Automotive AEC-Q200 Thick Film; Manufacturer: Panasonic; SizeZ_mm: 0.55mm; AEC Grade: Grade 0; VDC_V: 75V; TempCo: -100/+600ppm/°C; AEC Qualified: Yes; Power_W: 100mW; Tolerance_%: 5%

## Sheet TIDA-010967_QSPI_Flash.SchDoc: QSPI_FLASH
size 431 x 279 mm; Date: Not shown in title block; ApprovedBy: Not shown in title block; CheckedBy: Not shown in title block; Author: Not shown in title block; CompanyName: Not shown in title block; DrawnBy: Justin Yin; Engineer: Not shown in title block; Organization: Not shown in title block; Address1: Not shown in title block; Address2: Not shown in title block; Address3: Not shown in title block; Address4: Not shown in title block; DocumentNumber: 7; Revision: Use project parameter SCH_Rev; SheetNumber: 7; SheetTotal: 8; PageSetup: Record=PageOptions¦CenterHorizontal=True¦CenterVertical=True¦PrintScale=1.00¦XCorrection=1.00¦YCorrection=1.00¦PrintKind=0¦BorderSize=5000000¦LeftOffset=0¦BottomOffset=0¦Orientation=2¦PaperLength=1000¦PaperWidth=1000¦Scale=100¦PaperSource=15¦PrintQuality=600¦MediaType=1¦DitherType=10¦PaperKind=Letter¦PrintScaleMode=1
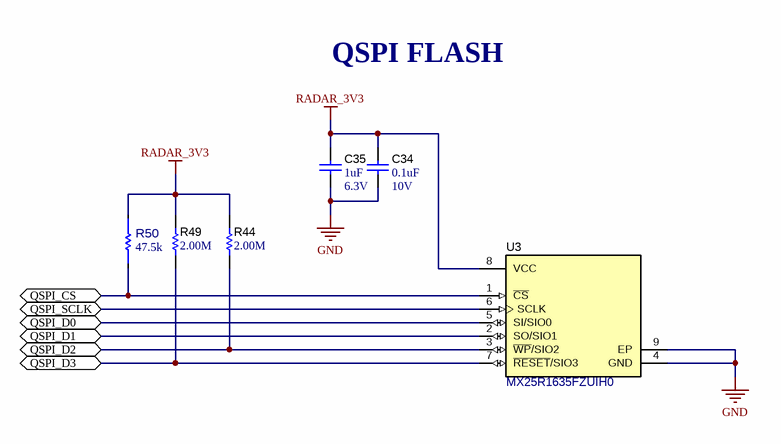
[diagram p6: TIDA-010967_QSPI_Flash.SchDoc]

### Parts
C34  Value2: 10V  ValueDisplayed: 0.1uF  [0201]  (hidden comment: GRM033C71A104KE14D)
C35  VDC_V: 6.3V  ValueDisplayed: 1uF  [0402L]  (hidden comment: GRM155R70J105KA12D)
R44  ValueDisplayed: 2.00M  [0402]  (hidden comment: CRCW04022M00FKED)
R49  ValueDisplayed: 2.00M  [0402]  (hidden comment: CRCW04022M00FKED)
R50  Res_ohm: 47.5k  [FP-AC0402FR-0747K5L_0402-MFG]  (hidden comment: AC0402FR-0747K5L)
U3  MX25R1635FZUIH0  [USON-8L]

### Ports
QSPI_CS (bidir), QSPI_D0 (bidir), QSPI_D1 (bidir), QSPI_D2 (bidir), QSPI_D3 (bidir), QSPI_SCLK (bidir)

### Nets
GND: C34.1 C35.2 U3.4(GND) U3.9(EP)
RADAR_3V3: C34.2 C35.1 R44.2 R49.2 R50.1 U3.8(VCC)
QSPI_CS: R50.2 U3.1(~{CS}) ; port QSPI_CS
QSPI_D0: U3.5(SI/SIO0) ; port QSPI_D0
QSPI_D1: U3.2(SO/SIO1) ; port QSPI_D1
QSPI_D2: R44.1 U3.3(~{WP}/SIO2) ; port QSPI_D2
QSPI_D3: R49.1 U3.7(~{RESET}/SIO3) ; port QSPI_D3
QSPI_SCLK: U3.6(SCLK) ; port QSPI_SCLK

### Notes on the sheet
- QSPI FLASH

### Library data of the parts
C34 = CMP-0064969-1: CAP, CERM, 0.1 uF, 10 V,+/- 10%, X7S, 0201; Manufacturer: MuRata; TaMin_C: -55°C; Polarized: N; SizeAreaWB_mm2: 2.08; Value1: Unknown; U/M: EA; Value: 0.1uF; TaMax_C: 125°C; SizeZ_mm: 0.26; SizeX_mm: 0.6; SizeY_mm: 0.3; SizeArea_mm2: 0.18; Cap_F: 100nF; AEC Category: Q200
C35 = CMP-0064947-2: as C18 on sheet TIDA-010967_Decoupling_caps
R44 R49 = CMP-0026245-2: as R4 on sheet TIDA-010967_xWRL6432_Chip
R50 = CMP-0095013-1: Res Thick Film 0402 47.5K Ohm 1% 1/16W ±100ppm/°C Molded SMD Paper T/R; Manufacturer: Yageo; VDC_V: 50V; SizeZ_mm: 0.37mm; AEC Grade: Grade 0; Power_W: 62.5mW; AEC Qualified: Yes
U3 = CMP-0078466-1: ULTRA LOW POWER, 16M-BIT [x 1/x 2/x 4] CMOS MXSMIO (SERIAL MULTI I/O) FLASH MEMORY, SON-8; Manufacturer: Macronix International Co., LTD; SizeArea_mm2: 6; SizeAreaWB_mm2: 12; SizeY_mm: 2; SizeZ_mm: 0.6; SizeX_mm: 3

## Sheet TIDA-010967_Hardware.SchDoc: HARDWARE
size 431 x 279 mm; Date: Not shown in title block; ApprovedBy: Not shown in title block; CheckedBy: Not shown in title block; Author: Not shown in title block; CompanyName: Not shown in title block; DrawnBy: Justin Yin; Engineer: Not shown in title block; Organization: Not shown in title block; Address1: Not shown in title block; Address2: Not shown in title block; Address3: Not shown in title block; Address4: Not shown in title block; DocumentNumber: 8; Revision: Use project parameter SCH_Rev; SheetNumber: 8; SheetTotal: 8; PageSetup: Record=PageOptions¦CenterHorizontal=True¦CenterVertical=True¦PrintScale=1.00¦XCorrection=1.00¦YCorrection=1.00¦PrintKind=0¦BorderSize=5000000¦LeftOffset=0¦BottomOffset=0¦Orientation=2¦PaperLength=1000¦PaperWidth=1000¦Scale=100¦PaperSource=15¦PrintQuality=600¦MediaType=1¦DitherType=10¦PaperKind=Letter¦PrintScaleMode=1
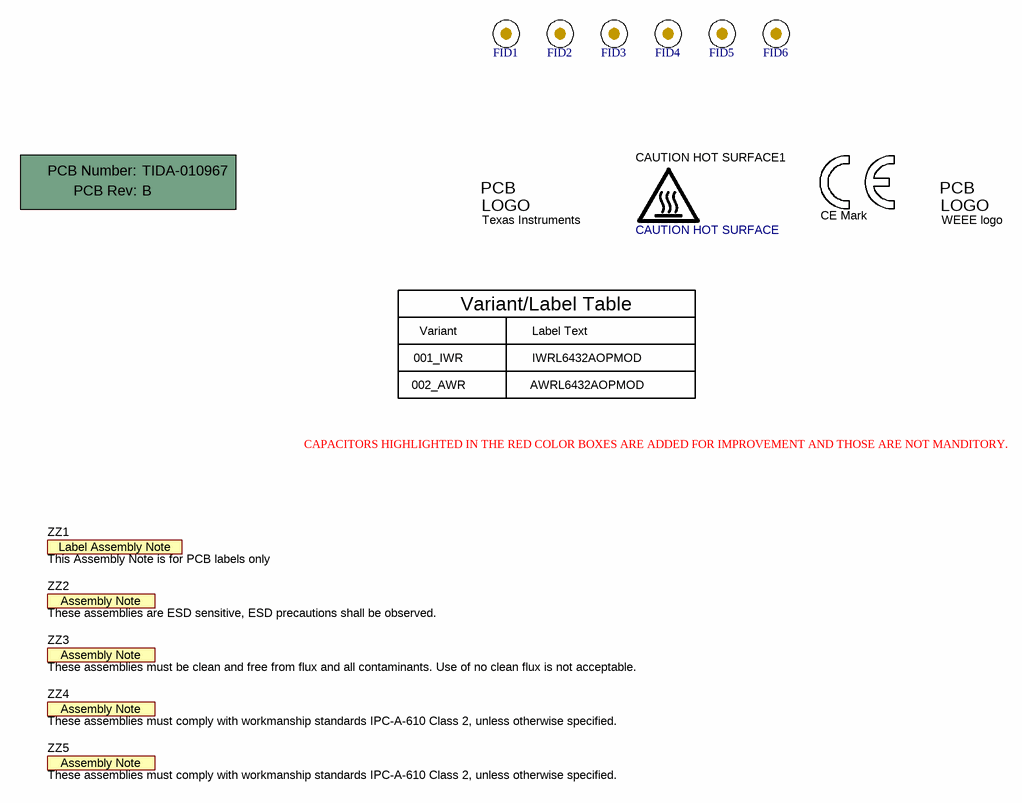
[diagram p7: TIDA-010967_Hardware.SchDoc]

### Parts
!PCB  Printed Circuit Board  (value not drawn)  (mechanical)
CAUTION_HOT_SURFACE1  CAUTION HOT SURFACE  [IEC_HotSurface_Small]  (no BOM)
FID1  Fiducial  [Fiducial10-20]  (value not drawn)
FID2  Fiducial  [Fiducial10-20]  (value not drawn)
FID3  Fiducial  [Fiducial10-20]  (value not drawn)
FID4  Fiducial  [Fiducial10-20]  (value not drawn)
FID5  Fiducial  [Fiducial10-20]  (value not drawn)
FID6  Fiducial  [Fiducial10-20]  (value not drawn)
Logo1  Texas Instruments  [TI_Symbol_Overlay_Small]  (no BOM)
Logo2  CE Mark  [CE_Mark_3MM5]  (no BOM)
Logo4  WEEE logo  [WEEE_Minimum]  (no BOM)
ZZ1  This Assembly Note is for PCB labels only  [AssemblyNoteLabel]  (no BOM)
ZZ2  These assemblies are ESD sensitive, ESD precautions shall be observed.  [AssemblyNote]  (no BOM)
ZZ3  These assemblies must be clean and free from flux and all contaminants. Use of no clean flux is not acceptable.  [AssemblyNote]  (no BOM)
ZZ4  These assemblies must comply with workmanship standards IPC-A-610 Class 2, unless otherwise specified.  [AssemblyNote]  (no BOM)
ZZ5  These assemblies must comply with workmanship standards IPC-A-610 Class 2, unless otherwise specified.  [AssemblyNote]  (no BOM)

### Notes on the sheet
- Variant
- 001_IWR
- Variant/Label Table
- Label Text
- IWRL6432AOPMOD
- 002_AWR
- AWRL6432AOPMOD
- CAPACITORS HIGHLIGHTED IN THE RED COLOR BOXES ARE ADDED FOR IMPROVEMENT AND THOSE ARE NOT MANDITORY.

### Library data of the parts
!PCB = CMP-0003618-2: Manufacturer: Any; PartNumber: TIDA-010967
CAUTION_HOT_SURFACE1 = CMP-0074837-2: IEC 61010-1 Hot Surface Warning; Manufacturer: Texas Instruments; SymbolCreator: a0412235; AEC Category: Q200; CompType: IC
FID1-FID6 = CMP-0077181-1: Fiducial mark.  There is nothing to buy or mount.
Logo1 = CMP-0074838-1: Texas Instrument Corporate Signature; SymbolCreator: a0412235; Lib Reference: TI_Logo
Logo2 = CMP-0074844-2: Manufacturer: Texas Instruments; SymbolCreator: a0412235; AEC Category: Q200; CompType: IC
Logo4 = CMP-0074769-1
ZZ1 = CMP-0003616-3
ZZ2 = CMP-0077236-1
ZZ3 = CMP-0077237-1
ZZ4 ZZ5 = CMP-0077238-1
